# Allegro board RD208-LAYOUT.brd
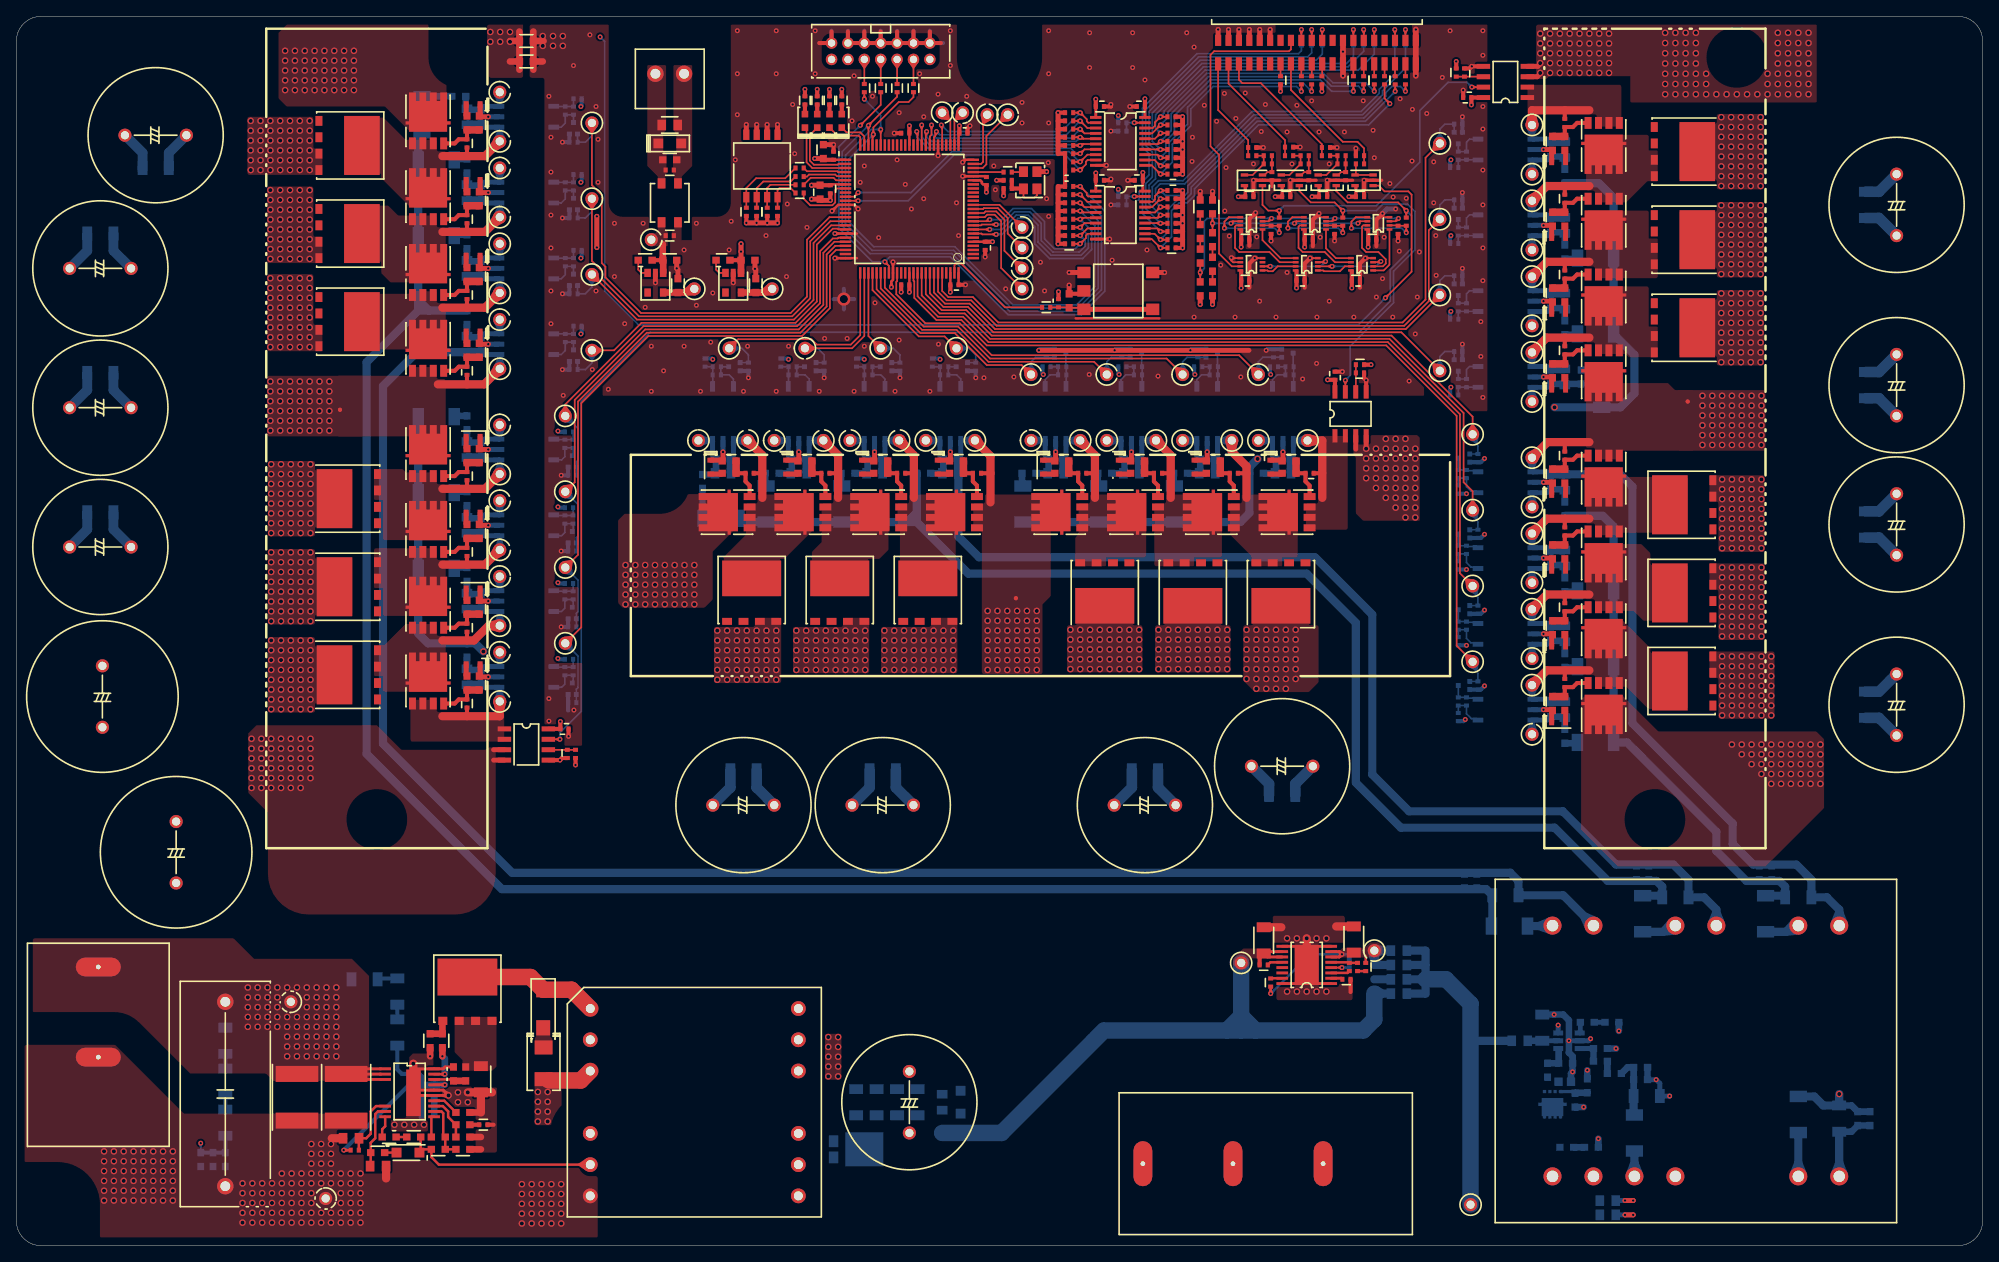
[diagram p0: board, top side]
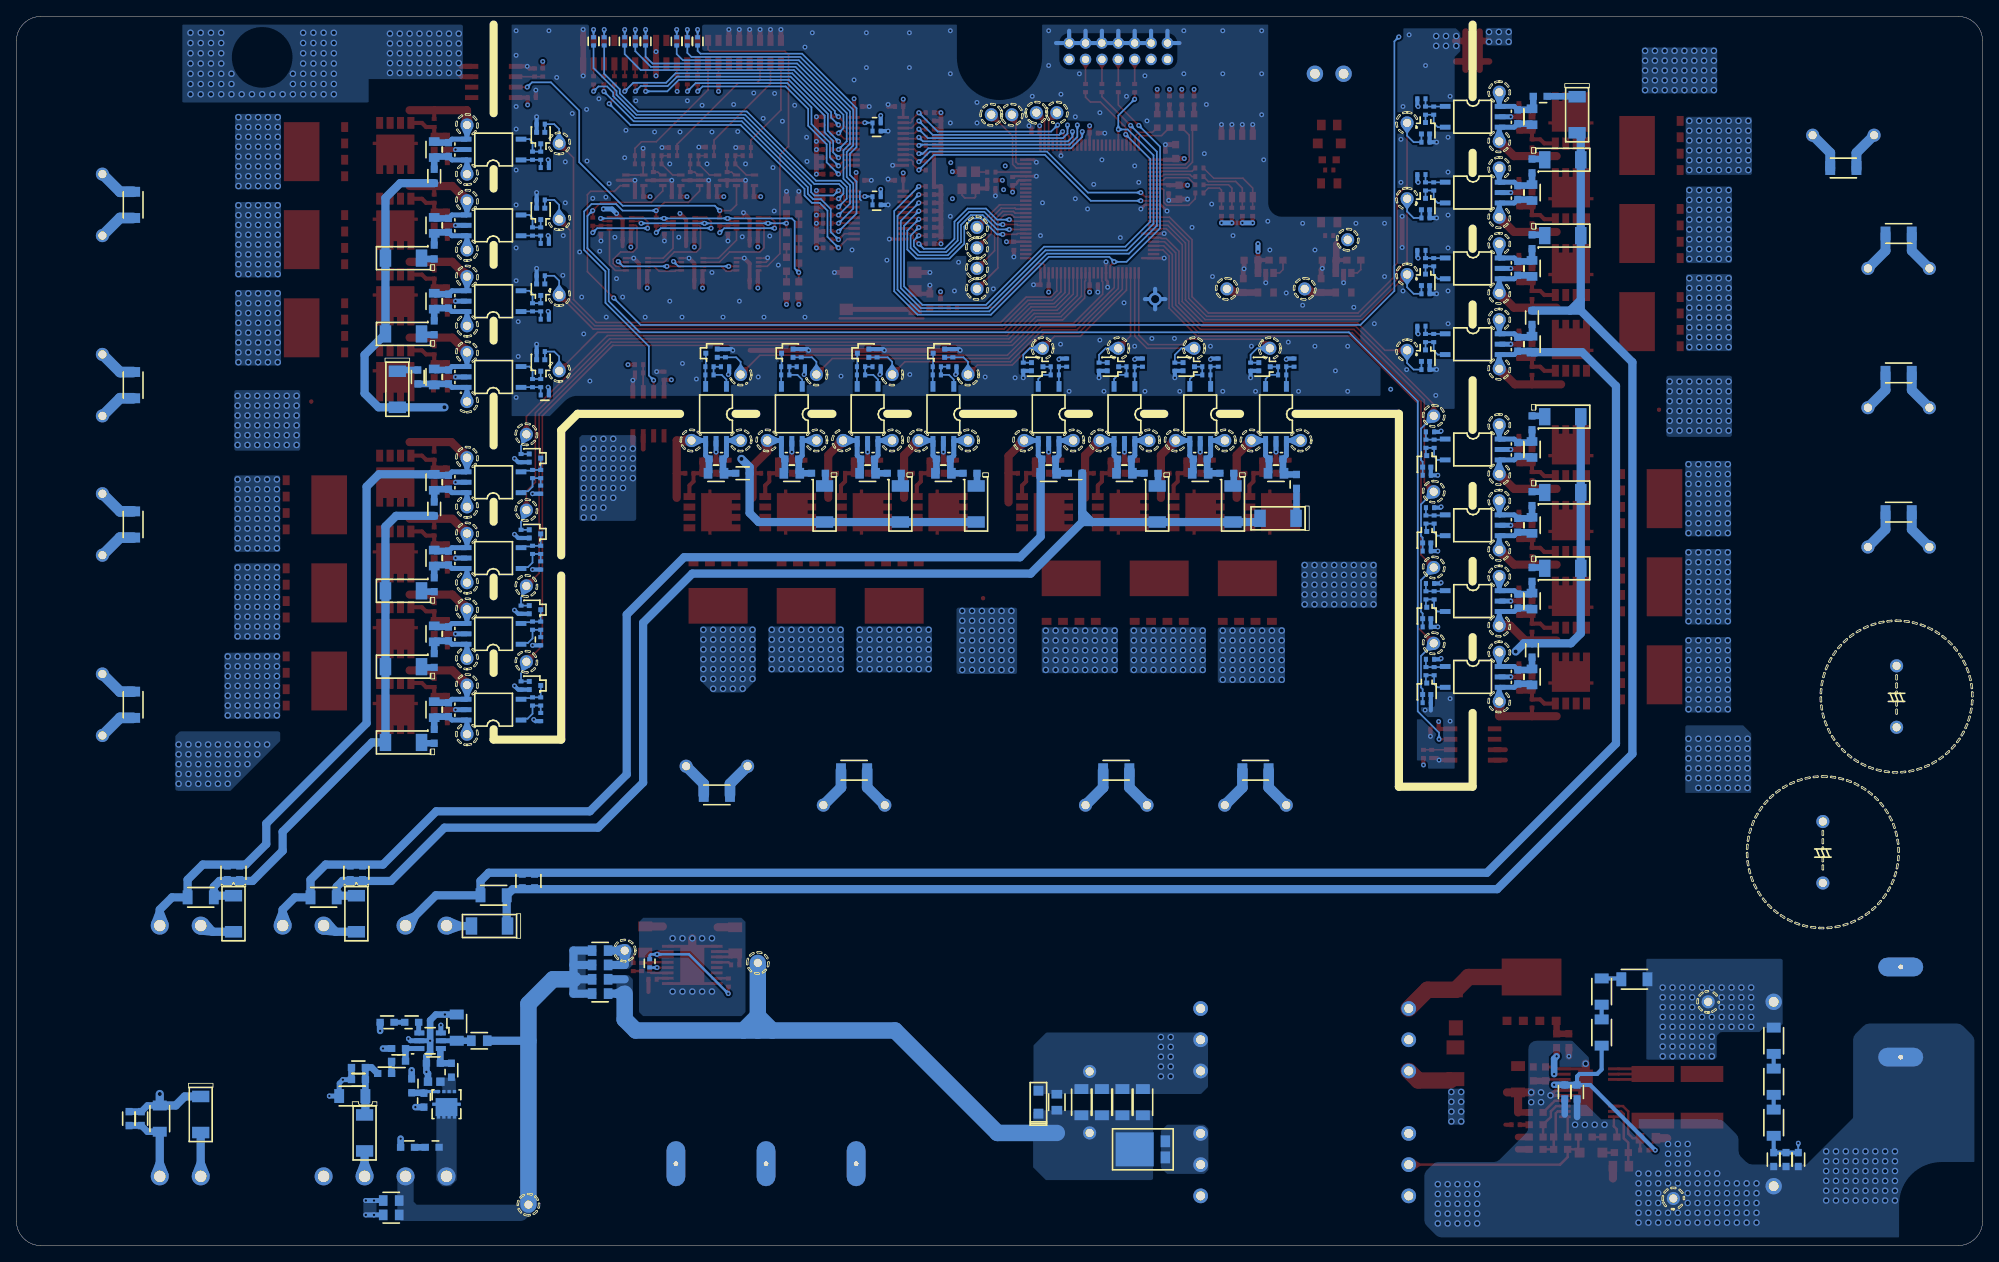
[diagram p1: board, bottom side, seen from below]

Outline 240 x 150 mm; copper layers: TOP, CONDUCTIVE2, CONDUCTIVE3, CONDUCTIVE4, CONDUCTIVE5, BOTTOM. Coordinates in mm from the lower left corner of the outline.
Outline path: 0,147 0.05,147.52 0.18,148.03 0.4,148.5 0.7,148.93 1.07,149.3 1.5,149.6 1.97,149.82 2.48,149.95 3,150 237,150 237.52,149.95 238.03,149.82 238.5,149.6 238.93,149.3 239.3,148.93 239.6,148.5 239.82,148.03 239.95,147.52 240,147 240,3 239.95,2.48 239.82,1.97 239.6,1.5 239.3,1.07 238.93,0.7 238.5,0.4 238.03,0.18 237.52,0.05 237,0 3,0 2.48,0.05 1.97,0.18 1.5,0.4 1.07,0.7 0.7,1.07 0.4,1.5 0.18,1.97 0.05,2.48 0,3 0,147

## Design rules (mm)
constraint set DEFAULT: 

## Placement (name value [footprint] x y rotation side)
C1  -  [C_27_0X10_5_P22_5_D__1]  25.5 18.5 270 top
C2  -  [C5750_R_SP]  34.25 18.1 270 top
C3  -  [C5750_R_SP]  40.25 18.1 270 top
C4  -  [C2125_R_SP]  44.15 9.7 0 top
C5  -  [C1608_R_SP]  48.5 13.25 180 top
C6  -  [C3216_R_SP]  102.5 17.5 90 bottom
C7  -  [CA_NICHEMI_D16_0_P7__1]  109 17.5 90 top
C8  -  [C1608_R_SP]  51 18.75 90 bottom
C9  -  [C3216_R_SP]  105 17.5 90 bottom
C10  -  [C1608_R_SP]  54.5 13.25 0 top
C11  -  [C1608_R_SP]  24 10.5 270 bottom
C12  -  [C1005_R_SP]  57 14.75 0 top
C13  -  [C1608_R_SP]  53.35 20.95 90 top
C14  -  [C2125_R_SP]  40.85 13.1 180 top
C15  -  [C3216_R_SP]  152.25 37.25 90 top
C16  -  [C3216_R_SP]  163.25 37.35 90 top
C17  -  [C3216_R_SP]  181.75 42.75 0 bottom
C18  -  [C3216_R_SP]  202.5 42.5 0 bottom
C19  -  [C3216_R_SP]  217.5 42.5 0 bottom
C20  -  [C3216_R_SP]  222.5 15.5 270 bottom
C21  -  [C3216_R_SP]  199 18.25 0 bottom
C22  -  [C1608_R_SP]  191.75 27.25 0 bottom
C23  -  [C1608_R_SP]  79.75 132.5 0 top
C24  -  [C1005_R_SP]  79.75 131.25 0 top
C25  -  [C1608_R_SP]  90.25 117.15 90 top
C27  -  [C1005_R_SP]  79.75 123.25 0 top
C28  -  [C1608_R_SP]  89.3 120.25 0 top
C29  -  [C1608_R_SP]  79.75 120.25 0 top
C30  -  [C1608_R_SP]  80.75 117.15 90 top
C31  -  [C1608_R_SP]  98.5 133.5 90 top
C32  -  [C1005_R_SP]  118.25 122 270 top
C33  -  [C1005_R_SP]  118.4 129.9 90 top
C34  -  [C1005_R_SP]  108.5 135.75 180 top
C35  -  [C1005_R_SP]  99.75 133 90 top
C36  -  [C1005_R_SP]  108.5 117.25 180 top
C37  -  [C1005_R_SP]  114.5 117.25 0 top
C38  -  [C1005_R_SP]  137 130 180 top
C39  -  [C1005_R_SP]  132.25 130 0 top
C40  -  [C1608_R_SP]  98.1 128.55 270 top
C41  -  [C1005_R_SP]  99.35 128.9 270 top
C42  -  [C1005_R_SP]  115.6 135.75 0 top
C43  -  [C1005_R_SP]  137.25 139 180 top
C44  -  [C1005_R_SP]  132.25 139 0 top
C45  -  [C1005_R_SP]  164 128 0 top
C46  -  [C1005_R_SP]  121 129 180 top
C47  -  [C2125_R_SP]  55 137.75 270 bottom
C48  -  [CA_NICHEMI_D16_0_P7__1]  17 135.5 0 top
C49  -  [CA_NICHEMI_D16_0_P7__1]  10.25 119.25 0 top
C50  -  [C2125_R_SP]  55 128.5 270 bottom
C53  -  [C2125_R_SP]  55 119.25 270 bottom
C54  -  [CA_NICHEMI_D16_0_P7__1]  10.25 102.25 0 top
C55  -  [C2125_R_SP]  55 110 270 bottom
C56  -  [CA_NICHEMI_D16_0_P7__1]  10.25 85.25 0 top
C57  -  [C2125_R_SP]  55 97.15 270 bottom
C58  -  [C2125_R_SP]  55 87.9 270 bottom
C59  -  [C2125_R_SP]  55 78.65 270 bottom
C60  -  [C2125_R_SP]  55 69.4 270 bottom
C61  -  [C1005_R_SP]  66.9 63.05 0 top
C62  -  [C2125_R_SP]  86.25 94.25 0 bottom
C63  -  [CA_NICHEMI_D16_0_P7__1]  88.75 53.75 0 top
C64  -  [C2125_R_SP]  95.5 94.25 0 bottom
C65  -  [CA_NICHEMI_D16_0_P7__1]  105.75 53.75 0 top
C66  -  [CA_D18_0_P7_5_D_SP]  19.5 48 90 top
C67  -  [CA_D18_0_P7_5_D_SP]  10.5 67 90 top
C68  -  [C2125_R_SP]  104.75 94.25 0 bottom
C69  -  [CA_NICHEMI_D16_0_P7__1]  137.75 53.75 0 top
C70  -  [C2125_R_SP]  114 94.25 0 bottom
C71  -  [CA_NICHEMI_D16_0_P7__1]  154.5 58.5 0 top
C72  -  [C2125_R_SP]  126.85 94.25 0 bottom
C73  -  [C2125_R_SP]  136.1 94.25 0 bottom
C74  -  [C2125_R_SP]  145.35 94.25 0 bottom
C75  -  [C1005_R_SP]  160.95 106.15 90 top
C76  -  [C2125_R_SP]  154.6 94.25 0 bottom
C77  -  [C2125_R_SP]  189 65.4 90 bottom
C78  -  [CA_NICHEMI_D16_0_P7__1]  229.5 66 90 top
C79  -  [C2125_R_SP]  189 74.65 90 bottom
C80  -  [CA_NICHEMI_D16_0_P7__1]  229.5 88 90 top
C81  -  [C2125_R_SP]  189 83.9 90 bottom
C82  -  [CA_NICHEMI_D16_0_P7__1]  229.5 105 90 top
C83  -  [C2125_R_SP]  189 93.15 90 bottom
C84  -  [CA_NICHEMI_D16_0_P7__1]  229.5 127 90 top
C85  -  [C2125_R_SP]  189 106 90 bottom
C86  -  [C2125_R_SP]  189 115.25 90 bottom
C87  -  [C2125_R_SP]  189 124.5 90 bottom
C88  -  [C2125_R_SP]  189 133.75 90 bottom
C89  -  [C1005_R_SP]  177.1 140.1 180 top
C90  -  [C1005_R_SP]  165.5 122.75 0 top
C91  -  [C1005_R_SP]  163.5 117.75 0 top
C92  -  [C1005_R_SP]  157.75 122.75 0 top
C93  -  [C1005_R_SP]  156.75 117.75 0 top
C94  -  [C1005_R_SP]  150 117.75 0 top
C95  -  [C1005_R_SP]  150 122.75 0 top
C96  -  [C1005_R_SP]  161.75 132 0 top
C97  -  [C1005_R_SP]  159.5 128 0 top
C98  -  [C1005_R_SP]  157.25 132 0 top
C99  -  [C1005_R_SP]  155 128 0 top
C100  -  [C1005_R_SP]  152.75 132 0 top
C101  -  [C1005_R_SP]  150.5 128 0 top
C102  -  [C1608_R_SP]  128.5 115.3 90 top
C103  -  [C1608_R_SP]  189.1 22.25 0 bottom
C104  -  [C1608_R_SP]  86.25 96 0 bottom
C105  -  [C1608_R_SP]  95.5 96 0 bottom
C106  -  [C1608_R_SP]  104.75 96 0 bottom
C107  -  [C1608_R_SP]  114 96 0 bottom
C108  -  [C1608_R_SP]  126.85 96 0 bottom
C109  -  [C1608_R_SP]  136.1 96 0 bottom
C110  -  [C1608_R_SP]  145.35 96 0 bottom
C111  -  [C1608_R_SP]  154.6 96 0 bottom
C112  -  [C1608_R_SP]  56.75 137.75 270 bottom
C113  -  [C1608_R_SP]  56.75 128.5 270 bottom
C114  -  [C1608_R_SP]  56.75 119.25 270 bottom
C115  -  [C1608_R_SP]  56.75 110 270 bottom
C116  -  [C1608_R_SP]  56.75 97.15 270 bottom
C117  -  [C1608_R_SP]  56.75 87.9 270 bottom
C118  -  [C1608_R_SP]  56.75 78.65 270 bottom
C119  -  [C1608_R_SP]  56.75 69.4 270 bottom
C120  -  [C1608_R_SP]  187.25 65.4 90 bottom
C121  -  [C1608_R_SP]  187.25 74.65 90 bottom
C122  -  [C1608_R_SP]  187.25 83.9 90 bottom
C123  -  [C1608_R_SP]  187.25 93.15 90 bottom
C124  -  [C1608_R_SP]  187.25 106 90 bottom
C125  -  [C1608_R_SP]  187.25 115.25 90 bottom
C126  -  [C1608_R_SP]  187.25 124.5 90 bottom
C127  -  [C1608_R_SP]  187.25 133.75 90 bottom
C128  -  [C1608_R_SP]  189.25 12 0 bottom
C129  -  [C3216_R_SP]  186.25 26.6 90 bottom
C130  -  [C1608_R_SP]  22.5 10.5 270 bottom
C131  -  [C3216_R_SP]  107.5 17.5 90 bottom
C132  -  [C3216_R_SP]  110 17.5 90 bottom
C133  -  [C1005_R_SP]  164 133 180 top
C134  -  [C1005_R_SP]  159.85 134 0 top
C135  -  [C1005_R_SP]  155.35 134.05 0 top
C136  -  [C1005_R_SP]  150.85 134 0 top
C137  -  [C2125_R_SP]  194.25 3.75 0 bottom
C138  -  [C2125_R_SP]  194.25 5.5 0 bottom
C139  -  [C1005_R_SP]  168.65 123.95 270 top
C140  -  [C1005_R_SP]  160.9 123.95 270 top
C141  -  [C1005_R_SP]  153.15 123.95 270 top
C142  -  [C1005_R_SP]  68 138.5 270 bottom
C143  -  [C1005_R_SP]  68 129.25 270 bottom
C144  -  [C1005_R_SP]  68 120 270 bottom
C145  -  [C1005_R_SP]  68 110.75 270 bottom
C146  -  [C1005_R_SP]  67.95 97.85 270 bottom
C147  -  [C1005_R_SP]  67.95 88.6 270 bottom
C148  -  [C1005_R_SP]  67.95 79.35 270 bottom
C149  -  [C1005_R_SP]  67.95 70.1 270 bottom
C150  -  [C1005_R_SP]  85.5 107.25 0 bottom
C151  -  [C1005_R_SP]  94.75 107.25 0 bottom
C152  -  [C1005_R_SP]  104 107.25 0 bottom
C153  -  [C1005_R_SP]  113.25 107.25 0 bottom
C154  -  [C1005_R_SP]  127.65 107.25 0 bottom
C155  -  [C1005_R_SP]  136.9 107.25 0 bottom
C156  -  [C1005_R_SP]  146.15 107.25 0 bottom
C157  -  [C1005_R_SP]  155.4 107.25 0 bottom
C158  -  [C1005_R_SP]  176 66.4 90 bottom
C159  -  [C1005_R_SP]  176 75.65 90 bottom
C160  -  [C1005_R_SP]  176 84.9 90 bottom
C161  -  [C1005_R_SP]  176 94.15 90 bottom
C162  -  [C1005_R_SP]  176 105.25 90 bottom
C163  -  [C1005_R_SP]  176 114.5 90 bottom
C164  -  [C1005_R_SP]  176 123.75 90 bottom
C165  -  [C1005_R_SP]  176 133 90 bottom
CN1  -  [OTB_640NS_B_2P_C_D_S_1]  10 34 270 top
CN2  -  [1843606_D_SP]  79.75 143 0 top
CN3  -  [FTSH_120_04_X_DH_A_A_1]  158.75 150.45 0 top
CN4  -  [878311420_D_SP]  105.5 145.75 180 top
CN5  -  [OTB_640NS_B_3P_C_D_S_1]  137.5 10 0 top
D1  -  [TO_3_2A1A_12_R_SP]  47.8 11.35 180 top
D2  -  [ON_TO_227_3LD_123_R__1]  102.5 11.75 180 bottom
D3  -  [TO_3_2A1S_R_SP]  115.25 17.5 270 bottom
D4  -  [VISHAY_DO_214AA_R_SP]  64.35 22.25 90 top
D6  -  [DIODES_D_FLAT_R_SP]  64.3 28.9 270 top
D7  -  [TO_3_4E1A_R_SP]  182.25 39 180 bottom
D8  -  [TO_3_4E1A_R_SP]  198.5 40.5 90 bottom
D9  -  [TO_3_4E1A_R_SP]  213.5 40.5 90 bottom
D10  -  [TO_3_4E1A_R_SP]  197.5 13.75 90 bottom
D11  -  [TO_3_4E1A_R_SP]  217.5 16 90 bottom
D13  -  [TO_3_2A1S_R_SP]  79.75 134.5 180 top
D14  -  [TO_3_4E1S_R_SP]  49.5 138 90 bottom
D15  -  [ON_PQFN4_8X8_2P_R_SP]  40.75 134.25 270 top
D16  -  [TO_3_4E1S_R_SP]  51.25 132.5 0 bottom
D17  -  [ON_PQFN4_8X8_2P_R_SP]  40.75 123.5 270 top
D18  -  [TO_3_4E1S_R_SP]  51.25 123.25 0 bottom
D19  -  [ON_PQFN4_8X8_2P_R_SP]  40.75 112.75 270 top
D20  -  [TO_3_4E1S_R_SP]  51.25 101.15 0 bottom
D21  -  [ON_PQFN4_8X8_2P_R_SP]  40.25 91.15 90 top
D22  -  [TO_3_4E1S_R_SP]  51.25 91.9 0 bottom
D23  -  [ON_PQFN4_8X8_2P_R_SP]  40.25 80.4 90 top
D24  -  [TO_3_4E1S_R_SP]  51.25 82.65 0 bottom
D25  -  [ON_PQFN4_8X8_2P_R_SP]  40.25 69.65 90 top
D26  -  [TO_3_4E1S_R_SP]  86 88.75 180 bottom
D27  -  [ON_PQFN4_8X8_2P_R_SP]  89.75 80 0 top
D28  -  [TO_3_4E1S_R_SP]  91.5 90.5 90 bottom
D29  -  [ON_PQFN4_8X8_2P_R_SP]  100.5 80 0 top
D30  -  [TO_3_4E1S_R_SP]  100.75 90.5 90 bottom
D31  -  [ON_PQFN4_8X8_2P_R_SP]  111.25 80 0 top
D32  -  [TO_3_4E1S_R_SP]  122.85 90.5 90 bottom
D33  -  [ON_PQFN4_8X8_2P_R_SP]  132.85 79.5 180 top
D34  -  [TO_3_4E1S_R_SP]  132.1 90.5 90 bottom
D35  -  [ON_PQFN4_8X8_2P_R_SP]  143.6 79.5 180 top
D36  -  [TO_3_4E1S_R_SP]  141.35 90.5 90 bottom
D37  -  [ON_PQFN4_8X8_2P_R_SP]  154.35 79.5 180 top
D38  -  [TO_3_4E1S_R_SP]  192.75 61.4 180 bottom
D39  -  [ON_PQFN4_8X8_2P_R_SP]  203.25 68.9 90 top
D40  -  [TO_3_4E1S_R_SP]  192.75 70.65 180 bottom
D41  -  [ON_PQFN4_8X8_2P_R_SP]  203.25 79.65 90 top
D42  -  [TO_3_4E1S_R_SP]  192.75 79.9 180 bottom
D43  -  [ON_PQFN4_8X8_2P_R_SP]  203.25 90.4 90 top
D44  -  [TO_3_4E1S_R_SP]  193.5 104.5 90 bottom
D45  -  [ON_PQFN4_8X8_2P_R_SP]  203.75 112 270 top
D46  -  [TO_3_4E1S_R_SP]  192.75 111.25 180 bottom
D47  -  [ON_PQFN4_8X8_2P_R_SP]  203.75 122.75 270 top
D48  -  [TO_3_4E1S_R_SP]  192.75 120.5 180 bottom
D49  -  [ON_PQFN4_8X8_2P_R_SP]  203.75 133.5 270 top
D50  -  [TO_ESC_R_SP]  55.75 139.25 0 top
D51  -  [TO_ESC_R_SP]  55.75 130 0 top
D52  -  [TO_ESC_R_SP]  55.75 120.75 0 top
D53  -  [TO_ESC_R_SP]  55.75 111.5 0 top
D54  -  [TO_ESC_R_SP]  55.75 98.65 0 top
D55  -  [TO_ESC_R_SP]  55.75 89.4 0 top
D56  -  [TO_ESC_R_SP]  55.75 80.15 0 top
D57  -  [TO_ESC_R_SP]  55.75 70.9 0 top
D58  -  [TO_ESC_R_SP]  84.75 95 90 top
D59  -  [TO_ESC_R_SP]  94 95 90 top
D60  -  [TO_ESC_R_SP]  103.25 95 90 top
D61  -  [TO_ESC_R_SP]  125.35 95 90 top
D62  -  [TO_ESC_R_SP]  112.5 95 90 top
D63  -  [TO_ESC_R_SP]  134.6 95 90 top
D64  -  [TO_ESC_R_SP]  143.85 95 90 top
D65  -  [TO_ESC_R_SP]  153.1 95 90 top
D66  -  [TO_ESC_R_SP]  188.25 63.9 180 top
D67  -  [TO_ESC_R_SP]  188.25 73.15 180 top
D68  -  [TO_ESC_R_SP]  188.25 82.4 180 top
D69  -  [TO_ESC_R_SP]  188.25 91.65 180 top
D70  -  [TO_ESC_R_SP]  188.25 104.5 180 top
D71  -  [TO_ESC_R_SP]  188.25 113.75 180 top
D72  -  [TO_ESC_R_SP]  188.25 123 180 top
D73  -  [TO_ESC_R_SP]  188.25 132.25 180 top
DR1  -  [ONEPOINT_R_SP]  39.5 102 270 top
DR2  -  [ONEPOINT_R_SP]  122 79 270 top
DR3  -  [ONEPOINT_R_SP]  204 103 0 top
DS1  -  [D_ROHM_1608_R_SP]  100.75 137.25 270 top
DS2  -  [D_ROHM_1608_R_SP]  99.25 137.25 270 top
DS3  -  [D_ROHM_1608_R_SP]  97.75 137.25 270 top
DS4  -  [D_ROHM_1608_R_SP]  96.25 137.25 270 top
FL1  -  [TDK_ACM4520_R_SP]  79.75 127.25 270 top
IC1  -  [LT_20_LEAD_PLASTIC_T_1]  48 18.65 270 top
IC2  -  [LT_TSSOP_16_FE_R_SP]  157.5 34.25 90 top
IC3  -  [LT_TSOT_23_6_R_SP]  189.5 25 270 bottom
IC4  -  [TO_SSOP5_P_0_95_R_SP]  87.5 117.5 180 top
IC5  -  [TO_SSOP5_P_0_95_R_SP]  78 117.5 180 top
IC6  -  [TO_TSSOP20B_R_SP]  134.75 125.75 270 top
IC7  -  [XI_VQFP100_R_SP]  109 126.5 90 top
IC8  -  [TO_TSSOP20B_R_SP]  134.75 134.75 270 top
IC9  -  [TI_DCK5_R_SP]  164.5 130 90 top
IC10  -  [TI_D8_R_SP]  62.25 61.15 270 top
IC11  -  [TI_D8_R_SP]  162.85 101.5 0 top
IC12  -  [TI_D8_R_SP]  181.75 142 90 top
IC13  -  [TO_SSOP8_P_0_50A_R_S_1]  166.25 124.75 90 top
IC14  -  [TO_SSOP8_P_0_50A_R_S_1]  164.25 119.75 90 top
IC15  -  [TO_SSOP8_P_0_50A_R_S_1]  158.5 124.75 90 top
IC16  -  [TO_SSOP8_P_0_50A_R_S_1]  150.75 119.75 90 top
IC17  -  [TO_SSOP8_P_0_50A_R_S_1]  157.5 119.75 90 top
IC18  -  [TO_SSOP8_P_0_50A_R_S_1]  150.75 124.75 90 top
IC19  -  [TI_DCK5_R_SP]  160 130 90 top
IC20  -  [TI_DCK5_R_SP]  155.5 130 90 top
IC21  -  [TI_DCK5_R_SP]  151 130 90 top
IC22  -  [ABRACON_ASE_3_2X2_5__1]  123.75 130 90 top
NOREF  -  []  156 10.38 90 top
NOREF#2  -  []  141 10.38 90 top
NOREF#3  -  []  111 36 0 top
PC1  -  [TO_11_4L1S_R_SP]  62.25 137.75 270 bottom
PC2  -  [TO_11_4L1S_R_SP]  62.25 128.5 270 bottom
PC3  -  [TO_11_4L1S_R_SP]  62.25 119.25 270 bottom
PC4  -  [TO_11_4L1S_R_SP]  62.25 110 270 bottom
PC5  -  [TO_11_4L1S_R_SP]  62.25 97.15 270 bottom
PC6  -  [TO_11_4L1S_R_SP]  62.25 87.9 270 bottom
PC7  -  [TO_11_4L1S_R_SP]  62.25 78.65 270 bottom
PC8  -  [TO_11_4L1S_R_SP]  62.25 69.4 270 bottom
PC9  -  [TO_11_4L1S_R_SP]  86.25 101.5 0 bottom
PC10  -  [TO_11_4L1S_R_SP]  95.5 101.5 0 bottom
PC11  -  [TO_11_4L1S_R_SP]  104.75 101.5 0 bottom
PC12  -  [TO_11_4L1S_R_SP]  114 101.5 0 bottom
PC13  -  [TO_11_4L1S_R_SP]  126.85 101.5 0 bottom
PC14  -  [TO_11_4L1S_R_SP]  136.1 101.5 0 bottom
PC15  -  [TO_11_4L1S_R_SP]  145.35 101.5 0 bottom
PC16  -  [TO_11_4L1S_R_SP]  154.6 101.5 0 bottom
PC17  -  [TO_11_4L1S_R_SP]  181.75 65.4 90 bottom
PC18  -  [TO_11_4L1S_R_SP]  181.75 74.65 90 bottom
PC19  -  [TO_11_4L1S_R_SP]  181.75 83.9 90 bottom
PC20  -  [TO_11_4L1S_R_SP]  181.75 93.15 90 bottom
PC21  -  [TO_11_4L1S_R_SP]  181.75 106 90 bottom
PC22  -  [TO_11_4L1S_R_SP]  181.75 115.25 90 bottom
PC23  -  [TO_11_4L1S_R_SP]  181.75 124.5 90 bottom
PC24  -  [TO_11_4L1S_R_SP]  181.75 133.75 90 bottom
Q1  -  [TO_2_8T1A_R_SP]  55.05 31.35 0 top
Q2  -  [TO_2_3X1S_R_SP]  187.5 17.25 0 bottom
Q3  -  [TO_2_5W1A_R_SP]  50.25 137.25 0 top
Q4  -  [TO_2_2H1B_GSD_123_R__1]  68 136.35 180 bottom
Q5  -  [TO_2_5W1A_R_SP]  50.25 128 0 top
Q6  -  [TO_2_2H1B_GSD_123_R__1]  68 127.1 180 bottom
Q7  -  [TO_2_5W1A_R_SP]  50.25 118.75 0 top
Q8  -  [TO_2_2H1B_GSD_123_R__1]  68 117.85 180 bottom
Q9  -  [TO_2_5W1A_R_SP]  50.25 109.5 0 top
Q10  -  [TO_2_2H1B_GSD_123_R__1]  68 108.6 180 bottom
Q11  -  [TO_2_5W1A_R_SP]  50.25 96.65 0 top
Q12  -  [TO_2_2H1B_GSD_123_R__1]  67.85 95.7 180 bottom
Q13  -  [TO_2_5W1A_R_SP]  50.25 87.4 0 top
Q14  -  [TO_2_2H1B_GSD_123_R__1]  67.85 86.45 180 bottom
Q15  -  [TO_2_5W1A_R_SP]  50.25 78.15 0 top
Q16  -  [TO_2_2H1B_GSD_123_R__1]  67.85 77.2 180 bottom
Q17  -  [TO_2_5W1A_R_SP]  50.25 68.9 0 top
Q18  -  [TO_2_2H1B_GSD_123_R__1]  67.85 67.95 180 bottom
Q19  -  [TO_2_5W1A_R_SP]  86.75 89.5 90 top
Q20  -  [TO_2_2H1B_GSD_123_R__1]  87.65 107.25 270 bottom
Q21  -  [TO_2_5W1A_R_SP]  96 89.5 90 top
Q22  -  [TO_2_2H1B_GSD_123_R__1]  96.9 107.25 270 bottom
Q23  -  [TO_2_5W1A_R_SP]  105.25 89.5 90 top
Q24  -  [TO_2_2H1B_GSD_123_R__1]  106.15 107.25 270 bottom
Q25  -  [TO_2_5W1A_R_SP]  114.5 89.5 90 top
Q26  -  [TO_2_2H1B_GSD_123_R__1]  115.4 107.25 270 bottom
Q27  -  [TO_2_5W1A_R_SP]  127.35 89.5 90 top
Q28  -  [TO_2_2H1B_GSD_123_R__1]  127.4 108.9 90 bottom
Q29  -  [TO_2_5W1A_R_SP]  136.6 89.5 90 top
Q30  -  [TO_2_2H1B_GSD_123_R__1]  136.65 108.9 90 bottom
Q31  -  [TO_2_5W1A_R_SP]  145.85 89.5 90 top
Q32  -  [TO_2_2H1B_GSD_123_R__1]  145.9 108.9 90 bottom
Q33  -  [TO_2_5W1A_R_SP]  155.1 89.5 90 top
Q34  -  [TO_2_2H1B_GSD_123_R__1]  155.15 108.9 90 bottom
Q35  -  [TO_2_5W1A_R_SP]  193.75 65.9 180 top
Q36  -  [TO_2_2H1B_GSD_123_R__1]  176.7 68.35 270 bottom
Q37  -  [TO_2_5W1A_R_SP]  193.75 75.15 180 top
Q38  -  [TO_2_2H1B_GSD_123_R__1]  176.7 77.6 270 bottom
Q39  -  [TO_2_5W1A_R_SP]  193.75 84.4 180 top
Q40  -  [TO_2_2H1B_GSD_123_R__1]  176.7 86.85 270 bottom
Q41  -  [TO_2_5W1A_R_SP]  193.75 93.65 180 top
Q42  -  [TO_2_2H1B_GSD_123_R__1]  176.7 96.1 270 bottom
Q43  -  [TO_2_5W1A_R_SP]  193.75 106.5 180 top
Q44  -  [TO_2_2H1B_GSD_123_R__1]  176 107.4 0 bottom
Q45  -  [TO_2_5W1A_R_SP]  193.75 115.75 180 top
Q46  -  [TO_2_2H1B_GSD_123_R__1]  176 116.65 0 bottom
Q47  -  [TO_2_5W1A_R_SP]  193.75 125 180 top
Q48  -  [TO_2_2H1B_GSD_123_R__1]  176 125.9 0 bottom
Q49  -  [TO_2_5W1A_R_SP]  193.75 134.25 180 top
Q50  -  [TO_2_2H1B_GSD_123_R__1]  176 135.15 0 bottom
R1  -  [R3216_R_SP]  42.5 32.5 0 bottom
R2  -  [R1608_R_SP]  44.1 11.35 0 top
R3  -  [R3216_R_SP]  46.5 31 270 bottom
R4  -  [R1608_R_SP]  45.5 13.25 180 top
R5  -  [R3216_R_SP]  25.5 25 270 bottom
R6  -  [R1608_R_SP]  51.5 11.75 0 top
R7  -  [R3216_R_SP]  46.5 26 270 bottom
R8  -  [R2125_R_SP]  113 17.5 270 bottom
R9  -  [R3216_R_SP]  25.5 20 270 bottom
R10  -  [R3216_R_SP]  25.5 15 270 bottom
R11  -  [R1608_R_SP]  49.5 18.75 90 bottom
R12  -  [R1608_R_SP]  51.5 13.25 180 top
R13  -  [R1608_R_SP]  54.5 11.75 0 top
R14  -  [R1608_R_SP]  54.5 14.75 0 top
R15  -  [R1608_R_SP]  25.5 10.5 270 bottom
R16  -  [R1608_R_SP]  54.5 16.25 180 top
R17  -  [R1608_R_SP]  52 25 90 top
R18  -  [R1608_R_SP]  54.85 20.95 90 top
R19  -  [R3216_R_SP]  56.7 20.3 270 top
R20  -  [R2125_R_SP]  168.75 30.75 0 bottom
R21  -  [R2125_R_SP]  168.75 36 0 bottom
R22  -  [R1005_R_SP]  152.25 34.25 0 top
R23  -  [R2125_R_SP]  168.75 32.5 0 bottom
R24  -  [R1005_R_SP]  164.7 34 90 top
R25  -  [R2125_R_SP]  168.75 34.25 0 bottom
R26  -  [R1005_R_SP]  162.35 32.5 0 top
R27  -  [R1005_R_SP]  163.7 34 90 top
R28  -  [R1608_R_SP]  195.05 21 180 bottom
R29  -  [R1608_R_SP]  193.35 22.5 180 bottom
R30  -  [R1608_R_SP]  186.9 21.4 270 bottom
R31  -  [R1608_R_SP]  198.25 20.25 0 bottom
R32  -  [R1608_R_SP]  194.75 27.25 0 bottom
R33  -  [R_WSL0603_R_SP]  189 20 0 bottom
R34  -  [R1608_R_SP]  193.35 24.05 0 bottom
R36  -  [R1608_R_SP]  86.25 120.25 180 top
R39  -  [R1608_R_SP]  76.75 120.25 180 top
R40  -  [R1005_R_SP]  141 128.75 180 top
R41  -  [R1005_R_SP]  141 127.75 180 top
R42  -  [R1005_R_SP]  141 126.75 180 top
R43  -  [R1005_R_SP]  141 125.75 180 top
R44  -  [R1005_R_SP]  141 124.75 180 top
R45  -  [R1005_R_SP]  141 123.75 180 top
R46  -  [R1005_R_SP]  141 122.75 180 top
R47  -  [R1005_R_SP]  141 121.75 180 top
R48  -  [R1005_R_SP]  128.5 129.25 0 top
R49  -  [R1005_R_SP]  128.5 128.25 0 top
R50  -  [R1005_R_SP]  128.5 127.25 0 top
R51  -  [R1005_R_SP]  128.5 126.25 0 top
R52  -  [R1005_R_SP]  128.5 125.25 0 top
R53  -  [R1005_R_SP]  128.5 124.25 0 top
R54  -  [R1005_R_SP]  128.5 123.25 0 top
R55  -  [R1005_R_SP]  128.5 122.25 0 top
R56  -  [R1005_R_SP]  159.35 142.2 270 top
R57  -  [R1005_R_SP]  154.3 142.2 270 top
R58  -  [R1005_R_SP]  141 137.75 180 top
R59  -  [R1005_R_SP]  141 136.75 180 top
R60  -  [R1005_R_SP]  141 135.75 180 top
R61  -  [R1005_R_SP]  141 134.75 180 top
R62  -  [R1005_R_SP]  141 133.75 180 top
R63  -  [R1005_R_SP]  141 132.75 180 top
R64  -  [R1005_R_SP]  141 131.75 180 top
R65  -  [R1005_R_SP]  141 130.75 180 top
R66  -  [R1005_R_SP]  128.5 138.25 0 top
R67  -  [R1005_R_SP]  128.5 137.25 0 top
R68  -  [R1005_R_SP]  128.5 136.25 0 top
R69  -  [R1005_R_SP]  128.5 135.25 0 top
R70  -  [R1005_R_SP]  128.5 134.25 0 top
R71  -  [R1005_R_SP]  128.5 133.25 0 top
R72  -  [R1005_R_SP]  128.5 132.25 0 top
R73  -  [R1005_R_SP]  128.5 131.25 0 top
R74  -  [R1005_R_SP]  121 130 0 top
R75  -  [R1005_R_SP]  107.5 141.25 270 top
R76  -  [R1005_R_SP]  109.5 141.25 270 top
R77  -  [R1005_R_SP]  105.5 141.25 270 top
R78  -  [R1005_R_SP]  103.5 141.25 270 top
R79  -  [R1005_R_SP]  121 131 180 top
R80  -  [R1608_R_SP]  54 140.25 180 bottom
R81  -  [R1005_R_SP]  68.5 139.95 180 bottom
R82  -  [R1608_R_SP]  55 131.75 90 bottom
R83  -  [R1005_R_SP]  68.5 130.7 180 bottom
R84  -  [R1608_R_SP]  55 122.5 90 bottom
R85  -  [R1005_R_SP]  68.5 121.45 180 bottom
R86  -  [R1608_R_SP]  55 113.25 90 bottom
R87  -  [R1005_R_SP]  68.5 112.2 180 bottom
R88  -  [R1608_R_SP]  55 100.4 90 bottom
R89  -  [R1005_R_SP]  67.45 99.3 0 bottom
R90  -  [R1608_R_SP]  55 91.15 90 bottom
R91  -  [R1005_R_SP]  67.45 90.05 0 bottom
R92  -  [R1608_R_SP]  55 81.9 90 bottom
R93  -  [R1005_R_SP]  67.45 80.8 0 bottom
R94  -  [R1608_R_SP]  55 72.65 90 bottom
R95  -  [R1005_R_SP]  67.45 71.55 0 bottom
R96  -  [R1608_R_SP]  83.75 93.25 270 bottom
R97  -  [R1005_R_SP]  84.05 107.75 270 bottom
R98  -  [R1608_R_SP]  92.25 94.25 180 bottom
R99  -  [R1005_R_SP]  93.3 107.75 270 bottom
R100  -  [R1005_R_SP]  102.55 107.75 270 bottom
R101  -  [R1608_R_SP]  101.5 94.25 180 bottom
R102  -  [R1005_R_SP]  111.8 107.75 270 bottom
R103  -  [R1608_R_SP]  110.75 94.25 180 bottom
R104  -  [R1608_R_SP]  123.6 94.25 180 bottom
R105  -  [R1005_R_SP]  125.75 107.25 0 bottom
R106  -  [R1608_R_SP]  132.85 94.25 180 bottom
R107  -  [R1005_R_SP]  135 107.25 0 bottom
R108  -  [R1608_R_SP]  142.1 94.25 180 bottom
R109  -  [R1005_R_SP]  144.25 107.25 0 bottom
R110  -  [R1608_R_SP]  151.35 94.25 180 bottom
R111  -  [R1005_R_SP]  153.5 107.25 0 bottom
R112  -  [R1608_R_SP]  189 62.15 270 bottom
R113  -  [R1005_R_SP]  176 64.5 90 bottom
R114  -  [R1608_R_SP]  189 71.4 270 bottom
R115  -  [R1005_R_SP]  176 73.75 90 bottom
R116  -  [R1608_R_SP]  189 80.65 270 bottom
R117  -  [R1005_R_SP]  176 83 90 bottom
R118  -  [R1608_R_SP]  189 89.9 270 bottom
R119  -  [R1005_R_SP]  176 92.25 90 bottom
R120  -  [R1608_R_SP]  191 106 90 bottom
R121  -  [R1005_R_SP]  175.5 103.8 0 bottom
R122  -  [R1608_R_SP]  189 112 270 bottom
R123  -  [R1005_R_SP]  175.5 113.05 0 bottom
R124  -  [R1608_R_SP]  189 121.25 270 bottom
R125  -  [R1005_R_SP]  175.5 122.3 0 bottom
R126  -  [R1608_R_SP]  189 130.5 270 bottom
R127  -  [R1005_R_SP]  175.5 131.55 0 bottom
R128  -  [R1608_R_SP]  146 116.75 90 top
R129  -  [R1608_R_SP]  144.5 116.75 90 top
R130  -  [R1608_R_SP]  146 119.75 90 top
R131  -  [R1608_R_SP]  144.5 120.75 90 top
R132  -  [R1608_R_SP]  146 122.75 90 top
R133  -  [R1608_R_SP]  144.5 123.75 90 top
R134  -  [R1608_R_SP]  146 126.75 90 top
R135  -  [R1608_R_SP]  144.5 126.75 90 top
R136  -  [R1005_R_SP]  161.75 133 0 top
R137  -  [R1005_R_SP]  159.85 133 0 top
R138  -  [R1005_R_SP]  162.25 130.5 90 top
R139  -  [R1005_R_SP]  157.25 133 0 top
R140  -  [R1005_R_SP]  155.35 133 0 top
R141  -  [R1005_R_SP]  157.75 130.5 90 top
R142  -  [R1005_R_SP]  152.75 133 0 top
R143  -  [R1005_R_SP]  150.85 133 0 top
R144  -  [R1005_R_SP]  153.25 130.5 90 top
R145  -  [R1005_R_SP]  100.75 139.75 270 top
R146  -  [R1005_R_SP]  99.25 139.75 270 top
R147  -  [R1005_R_SP]  97.75 139.75 270 top
R148  -  [R1005_R_SP]  96.25 139.75 270 top
R149  -  [R1005_R_SP]  89.1 126.15 90 top
R150  -  [R1005_R_SP]  90.35 126.15 90 top
R151  -  [R1005_R_SP]  91.65 126.15 90 top
R152  -  [R1005_R_SP]  92.9 126.15 90 top
R153  -  [R1005_R_SP]  127.2 115 270 top
R154  -  [R1608_R_SP]  191.75 19.5 270 bottom
R155  -  [R2125_R_SP]  183.5 25 0 bottom
R156  -  [R1005_R_SP]  169.55 142.2 270 top
R157  -  [R1005_R_SP]  165.75 142.2 270 top
R158  -  [R1005_R_SP]  164.45 142.2 270 top
R159  -  [R1005_R_SP]  163.2 142.2 270 top
R160  -  [R1005_R_SP]  169.55 146.95 90 bottom
R161  -  [R1005_R_SP]  168.25 146.95 90 bottom
R162  -  [R1005_R_SP]  165.75 146.95 90 bottom
R163  -  [R1005_R_SP]  164.45 146.95 90 bottom
R164  -  [R1005_R_SP]  163.2 146.95 90 bottom
R165  -  [R1005_R_SP]  159.4 146.95 90 bottom
R166  -  [R1005_R_SP]  158.1 146.95 90 bottom
R167  -  [R1005_R_SP]  156.85 146.95 90 bottom
R168  -  [R1608_R_SP]  87 95.75 0 top
R169  -  [R1608_R_SP]  96.25 95.75 0 top
R170  -  [R1608_R_SP]  105.5 95.75 0 top
R171  -  [R1608_R_SP]  114.75 95.75 0 top
R172  -  [R1608_R_SP]  127.6 95.75 0 top
R173  -  [R1608_R_SP]  136.85 95.75 0 top
R174  -  [R1608_R_SP]  146.1 95.75 0 top
R175  -  [R1608_R_SP]  155.35 95.75 0 top
R176  -  [R1608_R_SP]  56.5 137 270 top
R177  -  [R1608_R_SP]  56.5 127.75 270 top
R178  -  [R1608_R_SP]  56.5 118.5 270 top
R179  -  [R1608_R_SP]  56.5 109.25 270 top
R180  -  [R1608_R_SP]  56.5 96.4 270 top
R181  -  [R1608_R_SP]  56.5 87.15 270 top
R182  -  [R1608_R_SP]  56.5 77.9 270 top
R183  -  [R1608_R_SP]  56.5 68.65 270 top
R184  -  [R1608_R_SP]  187.5 66.15 90 top
R185  -  [R1608_R_SP]  187.5 75.4 90 top
R186  -  [R1608_R_SP]  187.5 84.65 90 top
R187  -  [R1608_R_SP]  187.5 93.9 90 top
R188  -  [R1608_R_SP]  187.5 106.75 90 top
R189  -  [R1608_R_SP]  187.5 116 90 top
R190  -  [R1608_R_SP]  187.5 125.25 90 top
R191  -  [R1608_R_SP]  187.5 134.5 90 top
R192  -  [R1005_R_SP]  164 132 0 top
R193  -  [R3216_R_SP]  17 131.5 0 bottom
R194  -  [R3216_R_SP]  10.25 123.5 0 bottom
R195  -  [R3216_R_SP]  10.25 106.5 0 bottom
R196  -  [R3216_R_SP]  10.25 89.5 0 bottom
R197  -  [R1608_R_SP]  192.25 12 0 bottom
R198  -  [R1005_R_SP]  168.3 142.2 270 top
R199  -  [R3216_R_SP]  88.75 58 0 bottom
R200  -  [R3216_R_SP]  105.75 58 0 bottom
R201  -  [R3216_R_SP]  137.75 58 0 bottom
R202  -  [R3216_R_SP]  154.5 55 0 bottom
R203  -  [R3216_R_SP]  225.75 66 90 bottom
R204  -  [R3216_R_SP]  225.75 88 90 bottom
R205  -  [R3216_R_SP]  225.75 105 90 bottom
R206  -  [R3216_R_SP]  225.75 127 90 bottom
R207  -  [R1608_R_SP]  50.5 25 270 top
R208  -  [R1608_R_SP]  190.25 17.75 270 bottom
R209  -  [R1005_R_SP]  125.7 114.5 180 top
R210  -  [R1005_R_SP]  95.6 131.5 0 top
R211  -  [R1005_R_SP]  95.6 130.45 0 top
R212  -  [R1005_R_SP]  95.6 129.45 0 top
R213  -  [R1005_R_SP]  95.6 128.45 0 top
R214  -  [R1005_R_SP]  55 134.5 270 top
R215  -  [R1005_R_SP]  55 125.25 270 top
R216  -  [R1005_R_SP]  55 116 270 top
R217  -  [R1005_R_SP]  55 106.75 270 top
R218  -  [R1005_R_SP]  55 93.9 270 top
R219  -  [R1005_R_SP]  55 84.65 270 top
R220  -  [R1005_R_SP]  55 75.4 270 top
R221  -  [R1005_R_SP]  55 66.15 270 top
R222  -  [R1005_R_SP]  89.5 94.25 0 top
R223  -  [R1005_R_SP]  98.75 94.25 0 top
R224  -  [R1005_R_SP]  108 94.25 0 top
R225  -  [R1005_R_SP]  117.25 94.25 0 top
R226  -  [R1005_R_SP]  130.1 94.25 0 top
R227  -  [R1005_R_SP]  139.35 94.25 0 top
R228  -  [R1005_R_SP]  148.6 94.25 0 top
R229  -  [R1005_R_SP]  157.85 94.25 0 top
R230  -  [R1005_R_SP]  189 68.65 90 top
R231  -  [R1005_R_SP]  189 77.9 90 top
R232  -  [R1005_R_SP]  189 87.15 90 top
R233  -  [R1005_R_SP]  189 96.4 90 top
R234  -  [R1005_R_SP]  189 109.25 90 top
R235  -  [R1005_R_SP]  189 118.5 90 top
R236  -  [R1005_R_SP]  189 127.75 90 top
R237  -  [R1005_R_SP]  189 137 90 top
R238  -  [R1005_R_SP]  167 142.2 270 top
R239  -  [R1005_R_SP]  158.1 142.2 270 top
R240  -  [R1005_R_SP]  156.85 142.2 270 top
R241  -  [R1005_R_SP]  135 128 0 bottom
R242  -  [R1005_R_SP]  135 127 0 bottom
R243  -  [R1005_R_SP]  135 137 0 bottom
R244  -  [R1005_R_SP]  135 136 0 bottom
R245  -  [R1608_R_SP]  55 137 270 top
R246  -  [R1608_R_SP]  55 127.75 270 top
R247  -  [R1608_R_SP]  55 118.5 270 top
R249  -  [R1608_R_SP]  55 109.25 270 top
R251  -  [R1608_R_SP]  55 96.4 270 top
R253  -  [R1608_R_SP]  55 87.15 270 top
R255  -  [R1608_R_SP]  55 77.9 270 top
R257  -  [R1608_R_SP]  55 68.65 270 top
R258  -  [R1608_R_SP]  87 94.25 0 top
R260  -  [R1608_R_SP]  96.25 94.25 0 top
R262  -  [R1608_R_SP]  105.5 94.25 0 top
R264  -  [R1608_R_SP]  127.6 94.25 0 top
R266  -  [R1608_R_SP]  114.75 94.25 0 top
R268  -  [R1608_R_SP]  136.85 94.25 0 top
R270  -  [R1608_R_SP]  146.1 94.25 0 top
R272  -  [R1608_R_SP]  155.35 94.25 0 top
R274  -  [R1608_R_SP]  189 66.15 90 top
R276  -  [R1608_R_SP]  189 75.4 90 top
R278  -  [R1608_R_SP]  189 84.65 90 top
R280  -  [R1608_R_SP]  189 93.9 90 top
R282  -  [R1608_R_SP]  189 106.75 90 top
R284  -  [R1608_R_SP]  189 116 90 top
R286  -  [R1608_R_SP]  189 125.25 90 top
R288  -  [R1608_R_SP]  189 134.5 90 top
R289  -  [R1005_R_SP]  68.25 60 270 top
R290  -  [R1005_R_SP]  67.25 60 270 top
R291  -  [R1005_R_SP]  164 107.5 0 top
R292  -  [R1005_R_SP]  164 106.5 180 top
R293  -  [R1005_R_SP]  175.75 143.15 90 top
R294  -  [R1005_R_SP]  176.75 143.15 270 top
R295  -  [R1005_R_SP]  153.1 32.1 90 top
R296  -  [R1005_R_SP]  162.7 34 90 top
R297  -  [R1005_R_SP]  162.7 34.45 90 bottom
R298  -  [R1608_R_SP]  62.25 147 180 top
R299  -  [R1608_R_SP]  62.25 144.5 180 top
R300  -  [R1608_R_SP]  198.25 21.75 0 bottom
R301  -  [R1608_R_SP]  178.25 44.5 90 bottom
R302  -  [R1608_R_SP]  176.75 44.5 90 bottom
R303  -  [R1608_R_SP]  199.25 45.5 90 bottom
R304  -  [R1608_R_SP]  197.75 45.5 90 bottom
R305  -  [R1608_R_SP]  214.25 45.5 90 bottom
R306  -  [R1608_R_SP]  212.75 45.5 90 bottom
R307  -  [R1608_R_SP]  224.75 15.5 270 bottom
R308  -  [R1608_R_SP]  226.25 15.5 270 bottom
R309  -  [R1005_R_SP]  169.65 124.95 90 top
R310  -  [R1005_R_SP]  161.9 124.95 90 top
R311  -  [R1005_R_SP]  154.15 124.95 90 top
R312  -  [R1005_R_SP]  41.3 11.65 180 top
R313  -  [R1005_R_SP]  68 134.65 180 bottom
R314  -  [R1005_R_SP]  68 125.4 180 bottom
R315  -  [R1005_R_SP]  68 116.15 180 bottom
R316  -  [R1005_R_SP]  68 106.9 180 bottom
R317  -  [R1005_R_SP]  67.85 94 180 bottom
R318  -  [R1005_R_SP]  67.85 84.75 180 bottom
R319  -  [R1005_R_SP]  67.85 75.5 180 bottom
R320  -  [R1005_R_SP]  67.85 66.25 180 bottom
R321  -  [R1005_R_SP]  89.35 107.25 270 bottom
R322  -  [R1005_R_SP]  98.6 107.25 270 bottom
R323  -  [R1005_R_SP]  107.85 107.25 270 bottom
R324  -  [R1005_R_SP]  117.1 107.25 270 bottom
R325  -  [R1005_R_SP]  125.7 108.9 90 bottom
R326  -  [R1005_R_SP]  134.95 108.9 90 bottom
R327  -  [R1005_R_SP]  144.2 108.9 90 bottom
R328  -  [R1005_R_SP]  153.45 108.9 90 bottom
R329  -  [R1005_R_SP]  178.4 68.35 270 bottom
R330  -  [R1005_R_SP]  178.4 77.6 270 bottom
R331  -  [R1005_R_SP]  178.4 86.85 270 bottom
R332  -  [R1005_R_SP]  178.4 96.1 270 bottom
R333  -  [R1005_R_SP]  176 109.1 0 bottom
R334  -  [R1005_R_SP]  176 118.35 0 bottom
R335  -  [R1005_R_SP]  176 127.6 0 bottom
R336  -  [R1005_R_SP]  176 136.85 0 bottom
R337  -  [R1005_R_SP]  67 138.5 270 bottom
R338  -  [R1005_R_SP]  67 129.25 270 bottom
R339  -  [R1005_R_SP]  67 120 270 bottom
R340  -  [R1005_R_SP]  67 110.75 270 bottom
R341  -  [R1005_R_SP]  66.95 97.85 270 bottom
R342  -  [R1005_R_SP]  66.95 88.6 270 bottom
R343  -  [R1005_R_SP]  66.95 79.35 270 bottom
R344  -  [R1005_R_SP]  66.95 70.1 270 bottom
R345  -  [R1005_R_SP]  85.5 106.25 0 bottom
R346  -  [R1005_R_SP]  94.75 106.25 0 bottom
R347  -  [R1005_R_SP]  104 106.25 0 bottom
R348  -  [R1005_R_SP]  113.25 106.25 0 bottom
R349  -  [R1005_R_SP]  127.65 106.25 0 bottom
R350  -  [R1005_R_SP]  136.9 106.25 0 bottom
R351  -  [R1005_R_SP]  146.15 106.25 0 bottom
R352  -  [R1005_R_SP]  155.4 106.25 0 bottom
R353  -  [R1005_R_SP]  177 66.4 90 bottom
R354  -  [R1005_R_SP]  177 75.65 90 bottom
R355  -  [R1005_R_SP]  177 84.9 90 bottom
R356  -  [R1005_R_SP]  177 94.15 90 bottom
R357  -  [R1005_R_SP]  177 105.25 90 bottom
R358  -  [R1005_R_SP]  177 114.5 90 bottom
R359  -  [R1005_R_SP]  177 123.75 90 bottom
R360  -  [R1005_R_SP]  177 133 90 bottom
RV1  -  [V2125_R_SP]  79.75 136.75 180 top
S1  -  [CHS_04TB_R_SP]  91 131.75 0 top
S2  -  [SKHMQKE010_R_SP]  134.5 116.5 90 top
T2  -  [750342424_D_SP]  205 23.75 0 top
T3  -  [SUMIDA_PQ2620_D_SP]  82.75 17.5 270 top
TP1  -  [TP_TH1_0_L1_6_D_SP]  33.5 29.75 0 top
TP2  -  [TP_TH1_0_L1_6_D_SP]  37.75 5.75 0 top
TP3  -  [TP_TH1_0_L1_6_D_SP]  149.5 34.5 90 top
TP4  -  [TP_TH1_0_L1_6_D_SP]  165.75 36 270 top
TP5  -  [TP_TH1_0_L1_6_D_SP]  177.5 5 0 top
TP6  -  [TP_TH1_0_L1_6_D_SP]  77.5 122.75 0 top
TP7  -  [TP_TH1_0_L1_6_D_SP]  92.25 116.75 180 top
TP8  -  [TP_TH1_0_L1_6_D_SP]  82.75 116.75 180 top
TP9  -  [TP_TH1_0_L1_6_D_SP]  122.75 116.75 90 top
TP10  -  [TP_TH1_0_L1_6_D_SP]  122.75 119.25 90 top
TP11  -  [TP_TH1_0_L1_6_D_SP]  122.75 121.75 90 top
TP12  -  [TP_TH1_0_L1_6_D_SP]  122.75 124.25 90 top
TP13  -  [TP_TH1_0_L1_6_D_SP]  121 138 90 top
TP14  -  [TP_TH1_0_L1_6_D_SP]  118.5 138 90 top
TP15  -  [TP_TH1_0_L1_6_D_SP]  115.5 138.25 90 top
TP16  -  [TP_TH1_0_L1_6_D_SP]  113 138.25 0 top
TP17  -  [TP_TH1_0_L1_6_D_SP]  70.25 137 180 top
TP18  -  [TP_TH1_0_L1_6_D_SP]  70.25 127.75 180 top
TP19  -  [TP_TH1_0_L1_6_D_SP]  70.25 118.5 180 top
TP20  -  [TP_TH1_0_L1_6_D_SP]  70.25 109.25 180 top
TP21  -  [TP_TH1_0_L1_6_D_SP]  67 101.25 180 top
TP22  -  [TP_TH1_0_L1_6_D_SP]  67 92 180 top
TP23  -  [TP_TH1_0_L1_6_D_SP]  67 82.75 180 top
TP24  -  [TP_TH1_0_L1_6_D_SP]  67 73.5 180 top
TP25  -  [TP_TH1_0_L1_6_D_SP]  59 140.75 180 top
TP26  -  [TP_TH1_0_L1_6_D_SP]  59 131.5 180 top
TP27  -  [TP_TH1_0_L1_6_D_SP]  59 122.25 180 top
TP28  -  [TP_TH1_0_L1_6_D_SP]  59 113 180 top
TP29  -  [TP_TH1_0_L1_6_D_SP]  59 100.15 180 top
TP30  -  [TP_TH1_0_L1_6_D_SP]  59 90.9 180 top
TP31  -  [TP_TH1_0_L1_6_D_SP]  59 81.65 180 top
TP32  -  [TP_TH1_0_L1_6_D_SP]  59 72.4 180 top
TP33  -  [TP_TH1_0_L1_6_D_SP]  87 109.5 270 top
TP34  -  [TP_TH1_0_L1_6_D_SP]  96.25 109.5 270 top
TP35  -  [TP_TH1_0_L1_6_D_SP]  105.5 109.5 270 top
TP36  -  [TP_TH1_0_L1_6_D_SP]  114.75 109.5 270 top
TP37  -  [TP_TH1_0_L1_6_D_SP]  123.85 106.3 270 top
TP38  -  [TP_TH1_0_L1_6_D_SP]  133.1 106.3 270 top
TP39  -  [TP_TH1_0_L1_6_D_SP]  142.35 106.3 270 top
TP40  -  [TP_TH1_0_L1_6_D_SP]  151.6 106.3 270 top
TP41  -  [TP_TH1_0_L1_6_D_SP]  83.25 98.25 270 top
TP42  -  [TP_TH1_0_L1_6_D_SP]  92.5 98.25 270 top
TP43  -  [TP_TH1_0_L1_6_D_SP]  101.75 98.25 270 top
TP44  -  [TP_TH1_0_L1_6_D_SP]  111 98.25 270 top
TP45  -  [TP_TH1_0_L1_6_D_SP]  123.85 98.25 270 top
TP46  -  [TP_TH1_0_L1_6_D_SP]  133.1 98.25 270 top
TP47  -  [TP_TH1_0_L1_6_D_SP]  142.35 98.25 270 top
TP48  -  [TP_TH1_0_L1_6_D_SP]  151.6 98.25 270 top
TP49  -  [TP_TH1_0_L1_6_D_SP]  177.75 71.25 0 top
TP50  -  [TP_TH1_0_L1_6_D_SP]  177.75 80.5 0 top
TP51  -  [TP_TH1_0_L1_6_D_SP]  177.75 89.75 0 top
TP52  -  [TP_TH1_0_L1_6_D_SP]  177.75 99 0 top
TP53  -  [TP_TH1_0_L1_6_D_SP]  173.75 106.75 0 top
TP54  -  [TP_TH1_0_L1_6_D_SP]  173.75 116 0 top
TP55  -  [TP_TH1_0_L1_6_D_SP]  173.75 125.25 0 top
TP56  -  [TP_TH1_0_L1_6_D_SP]  173.75 134.5 0 top
TP57  -  [TP_TH1_0_L1_6_D_SP]  185 62.4 0 top
TP58  -  [TP_TH1_0_L1_6_D_SP]  185 71.65 0 top
TP59  -  [TP_TH1_0_L1_6_D_SP]  185 80.9 0 top
TP60  -  [TP_TH1_0_L1_6_D_SP]  185 90.15 0 top
TP61  -  [TP_TH1_0_L1_6_D_SP]  185 103 0 top
TP62  -  [TP_TH1_0_L1_6_D_SP]  185 112.25 0 top
TP63  -  [TP_TH1_0_L1_6_D_SP]  185 121.5 0 top
TP64  -  [TP_TH1_0_L1_6_D_SP]  185 130.75 0 top
TP65  -  [TP_TH1_0_L1_6_D_SP]  59 134.75 180 top
TP66  -  [TP_TH1_0_L1_6_D_SP]  59 125.5 180 top
TP67  -  [TP_TH1_0_L1_6_D_SP]  59 116.25 180 top
TP68  -  [TP_TH1_0_L1_6_D_SP]  59 107 180 top
TP69  -  [TP_TH1_0_L1_6_D_SP]  59 94.15 180 top
TP70  -  [TP_TH1_0_L1_6_D_SP]  59 84.9 180 top
TP71  -  [TP_TH1_0_L1_6_D_SP]  59 75.65 180 top
TP72  -  [TP_TH1_0_L1_6_D_SP]  59 66.4 180 top
TP73  -  [TP_TH1_0_L1_6_D_SP]  89.25 98.25 270 top
TP74  -  [TP_TH1_0_L1_6_D_SP]  98.5 98.25 270 top
TP75  -  [TP_TH1_0_L1_6_D_SP]  107.75 98.25 270 top
TP76  -  [TP_TH1_0_L1_6_D_SP]  117 98.25 270 top
TP77  -  [TP_TH1_0_L1_6_D_SP]  129.85 98.25 270 top
TP78  -  [TP_TH1_0_L1_6_D_SP]  139.1 98.25 270 top
TP79  -  [TP_TH1_0_L1_6_D_SP]  148.35 98.25 270 top
TP80  -  [TP_TH1_0_L1_6_D_SP]  157.6 98.25 270 top
TP81  -  [TP_TH1_0_L1_6_D_SP]  185 68.4 0 top
TP82  -  [TP_TH1_0_L1_6_D_SP]  185 77.65 0 top
TP83  -  [TP_TH1_0_L1_6_D_SP]  185 86.9 0 top
TP84  -  [TP_TH1_0_L1_6_D_SP]  185 96.15 0 top
TP85  -  [TP_TH1_0_L1_6_D_SP]  185 109 0 top
TP86  -  [TP_TH1_0_L1_6_D_SP]  185 118.25 0 top
TP87  -  [TP_TH1_0_L1_6_D_SP]  185 127.5 0 top
TP88  -  [TP_TH1_0_L1_6_D_SP]  185 136.75 0 top

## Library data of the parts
C1 = ECWFG2J105P1
C2 C3 = 2220CC104KAT1A: alternate symbols: (C2_C5750_R_SP,C3_C5750_R_SP)
C4 C14 C137 C138 = GRM21BR61H475KE51L
C5 C10 = GRM1885C2A470JA01D
C6 C9 C131 C132 = GRM31CC81E226KE11L
C7 = EKY-500ELL471ML15S
C8 C11 C13 C130 = GRM1885C1H102JA01J
C12 C24 C27 C32-C39 C41-C46 C61 C75 C89-C95 C97 C99 C101 C133-C136 C139-C141 = GRM155R71E104KE14D
C15-C21 C129 = GRM31CR71E106MA12K
C22 C103 = GRM1885C1H103JA01J
C23 C25 C28-C31 C40 C102 = GRM188R61A106ME69D
C47 C50 C53 C55 C57-C60 C62 C64 C68 C70 C72-C74 C76 C77 C79 C81 C83 C85-C88 = GRM21BR71E225KE11L
C48 C49 C54 C56 C63 C65 C69 C71 C78 C80 C82 C84 = EKMQ251ELL101ML25S
C66 C67 = EKXF451ELL470MM25S
C96 C98 C100 = GRM1555C1H100RA01D
C104-C127 = C1608X7R1H104K080AA
C128 = 06031A151FAT2A
C142-C165 = GRM1555C1H471JA01J
CN1 = OTB-640NS-B-2P-C
CN2 = 1843606
CN3 = FTSH-120-04-F-DH-A-AEP
CN4 = 878311420
CN5 = OTB-640NS-B-3P-C
D1 = CRH01-12
D2 = FSV20100V-123
D3 = CRZ18
D4 = SMBJ188A-E3_52
D6 = US1MDFQ-13
D7-D11 = CMS10
D13 = CRS30I30A
D14 D16 D18 D20 D22 D24 D26 D28 D30 D32 D34 D36 D38 D40 D42 D44 D46 D48 = CMF01A_LQ_M
D15 D17 D19 D21 D23 D25 D27 D29 D31 D33 D35 D37 D39 D41 D43 D45 D47 D49 = FFSM2065B
D50-D73 = BAS516_L3F
DR1-DR3 = ONEPOINT
DS1-DS4 = SMLD12EN1WT86
FL1 = ACM4520-421-2P-T000
IC1 = LT-20-Lead-Plastic-TSSOP-FE-R-SP-17p
IC2 = LT3086IFE_PBF
IC3 = LTC3803HS6-5_TRMPBF
IC4 = TCR3UF33A
IC5 = TCR3UF18A
IC6 IC8 = TC7MPB9307FT
IC7 = XC2C256-7VQG100C
IC9 IC19-IC21 = OPA172IDCKT
IC10-IC12 = TMCS1100A1QDRQ1
IC13 IC15 IC18 = TC75W57FK
IC14 IC16 IC17 = TC7W08FK
IC22 = ASE-20.000MHZ-LC-T
PC1-PC24 = TLP152_TPL_E
Q1 = TK17V65W
Q2 = TPN7R006PL_L1Q
Q3 Q5 Q7 Q9 Q11 Q13 Q15 Q17 Q19 Q21 Q23 Q25 Q27 Q29 Q31 Q33 Q35 Q37 Q39 Q41 Q43 Q45 Q47 Q49 = TPH9R00CQ5
Q4 Q6 Q8 Q10 Q12 Q14 Q16 Q18 Q20 Q22 Q24 Q26 Q28 Q30 Q32 Q34 Q36 Q38 Q40 Q42 Q44 Q46 Q48 Q50 = SSM3K15AFS-123
R1 R3 R5 R7 R9 R10 R193-R196 R199-R206 = HV73V2BTTD4703D
R2 R80 R82 R84 R88 R90 R92 R96 R98 R101 R104 R106 R108 R112 R114 R116 R120 R122 R124 = ERJ3EKF10R0V
R4 R14 R34 R36 R39 R207 R208 R301-R308 = ERJ3EKF1002V
R6 = ERA3APB6042V
R8 = AAC-0805
R11 R15 = RK73H1JRTTD1502D
R12 = ERJ3EKF1203V
R13 = ERA3AEB4991V
R16 = ERA3ARB5622V
R17 R86 R94 R103 R110 R118 R126 R154 R245-R247 R249 R251 R253 R255 R257 R258 R260 R262 R264 R266 R268 R270 R272 R274 R276 R278 R280 R282 R284 R286 R288 R298 R299 = ERJ3GEY0R00V
R18 = ERJ3EKF1000V
R19 = KRL1632E-M-R150-F-T5
R20 R21 R23 R25 = ERJ6GEY0R00V
R22 R295 = ERJ2RKF1003X
R24 R297 = ERJ2RKF2703X
R26 = ERJ2RKF3300X
R27 = ERJ2RKF2202X
R28 = ERJ3EKF3302V
R29 = ERJ3EKF5102V
R30 = ERJ3EKF4701V
R31 R300 = ERJ3EKF1001V
R32 = ERJ3EKF2202V
R33 = WSLP0603R0470FEA
R40-R55 R58-R73 R136 R139 R142 R149-R153 R214-R237 R241 R243 R313-R336 = ERJ2RKF1002X
R56 R57 R74 R137 R140 R143 R156-R167 R192 R198 R238-R240 R242 R244 R309-R312 = ERJ2GE0R00X
R75-R79 = ERJ2RKF22R0X
R81 R83 R85 R87 R89 R91 R93 R95 R97 R99 R100 R102 R105 R107 R109 R111 R113 R115 R117 R119 R121 R123 R125 R127 = ERJ2RKF2700X
R128 R129 R134 R135 = ERJ3RBD2002V
R130-R133 = ERJ3RBD3002V
R138 R141 R144 = ERJ2RKF2002X
R145-R148 R337-R360 = ERJ2RKF1001X
R155 = ERJP06J471V
R168-R191 = ERJ3EKF22R0V
R197 = ERJ3EKF2200V
R209-R213 = ERJ2RKF1000X
R289-R294 = RK73G1ETTP1002D
R296 = ERJ2RKF1603X
RV1 = NV73A2ATTE8.2
S1 = CHS-04TB
S2 = SKHMQKE010
T2 = 750342424
T3 = 11328-T074
TP1-TP88 = TP-TH1.0-L1.6

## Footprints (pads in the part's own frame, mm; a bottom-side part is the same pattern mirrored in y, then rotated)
1843606_D_SP
  round 2 hole 1.2: 1(1.75,0) 2(-1.75,0)
750342424_D_SP
  round 2.2 hole 1.4: 1(-17.5,-15.3) 2(-12.5,-15.3) 3(-7.5,-15.3) 4(-2.5,-15.3) 7(12.5,-15.3) 8(17.5,-15.3) 9(17.5,15.3) 10(12.5,15.3) 12(2.5,15.3) 13(-2.5,15.3) 15(-12.5,15.3) 16(-17.5,15.3)
878311420_D_SP
  round 0.01 hole 1 unplated: (5,0)
  round 1.4 hole 0.9: 1(-6,-1) 2(-6,1) 3(-4,-1) 4(-4,1) 5(-2,-1) 6(-2,1) 7(0,-1) 8(0,1) 9(2,-1) 10(2,1) 11(4,-1) 12(4,1) 13(6,-1) 14(6,1)
ABRACON_ASE_3_2X2_5__1
  rect 1.3x1.1 smd: 1(-1.05,-0.825) 2(1.05,-0.825) 3(1.05,0.825) 4(-1.05,0.825)
C1005_R_SP
  rect 0.5x0.6 smd: 1(-0.5,0) 2(0.5,0)
C1608_R_SP
  rect 0.9x0.85 smd: 1(-0.85,0) 2(0.85,0)
C2125_R_SP
  rect 1.05x1.3 smd: 1(-0.975,0) 2(0.975,0)
C3216_R_SP
  rect 1.2x1.7 smd: 1(-1.6,0) 2(1.6,0)
C5750_R_SP
  custom 0.487x0.487 smd: 1(-2.85,0) 2(2.85,0)
C_27_0X10_5_P22_5_D__1
  round 2 hole 1.2: 1(-11.25,0) 2(11.25,0)
CA_D18_0_P7_5_D_SP
  round 1.6 hole 1: 1(-3.75,0) 2(3.75,0)
CA_NICHEMI_D16_0_P7__1
  round 1.6 hole 1: 1(-3.75,0) 2(3.75,0)
CHS_04TB_R_SP
  rect 0.76x1.27 smd: 1(-1.905,-3.81) 2(-0.635,-3.81) 3(0.635,-3.81) 4(1.905,-3.81) 5(1.905,3.81) 6(0.635,3.81) 7(-0.635,3.81) 8(-1.905,3.81)
D_ROHM_1608_R_SP
  rect 0.8x0.8 smd: A(-0.825,0) K(0.825,0)
DIODES_D_FLAT_R_SP
  rect 1.85x1.7 smd: A(-2.325,0) K(2.325,0)
FTSH_120_04_X_DH_A_A_1
  rect 0.75x1.36 smd: 1(12.065,-3.375) 3(10.795,-3.375) 5(9.525,-3.375) 7(8.255,-3.375) 9(6.985,-3.375) 11(5.715,-3.375) 13(4.445,-3.375) 15(3.175,-3.375) 17(1.905,-3.375) 19(0.635,-3.375) 21(-0.635,-3.375) 23(-1.905,-3.375) 25(-3.175,-3.375) 27(-4.445,-3.375) 29(-5.715,-3.375) 31(-6.985,-3.375) 33(-8.255,-3.375) 35(-9.525,-3.375) 37(-10.795,-3.375) 39(-12.065,-3.375)
  rect 0.75x1.62 smd: 2(12.065,-6.245) 4(10.795,-6.245) 6(9.525,-6.245) 8(8.255,-6.245) 10(6.985,-6.245) 12(5.715,-6.245) 14(4.445,-6.245) 16(3.175,-6.245) 18(1.905,-6.245) 20(0.635,-6.245) 22(-0.635,-6.245) 24(-1.905,-6.245) 26(-3.175,-6.245) 28(-4.445,-6.245) 30(-5.715,-6.245) 32(-6.985,-6.245) 34(-8.255,-6.245) 36(-9.525,-6.245) 38(-10.795,-6.245) 40(-12.065,-6.245)
LT_20_LEAD_PLASTIC_T_1
  rect 0.35x1.425 smd: 1(-2.925,-2.987) 2(-2.275,-2.987) 3(-1.625,-2.987) 8(1.625,-2.987) 9(2.275,-2.987) 10(2.925,-2.987) 11(2.925,2.987) 12(2.275,2.987) 13(1.625,2.987) 14(0.975,2.987) 15(0.325,2.987) 16(-0.325,2.987) 17(-0.975,2.987) 18(-1.625,2.987) 19(-2.275,2.987) 20(-2.925,2.987)
  custom 0.445x0.445 smd: 21(0,0.47)
LT_TSOT_23_6_R_SP
  rect 0.62x1.22 smd: 1(-0.95,-1.31) 2(0,-1.31) 3(0.95,-1.31) 4(0.95,1.31) 5(0,1.31) 6(-0.95,1.31)
LT_TSSOP_16_FE_R_SP
  rect 0.35x1.425 smd: 1(-2.275,-2.987) 2(-1.625,-2.987) 3(-0.975,-2.987) 4(-0.325,-2.987) 5(0.325,-2.987) 6(0.975,-2.987) 7(1.625,-2.987) 8(2.275,-2.987) 9(2.275,2.987) 10(1.625,2.987) 11(0.975,2.987) 12(0.325,2.987) 13(-0.325,2.987) 14(-0.975,2.987) 15(-1.625,2.987) 16(-2.275,2.987)
  custom 0.735x0.735 smd: 17(0,0)
ON_PQFN4_8X8_2P_R_SP
  rect 1.2x0.85 smd: 1(-3,-3.825) 2(-1,-3.825) 3(1,-3.825) 4(3,-3.825)
  custom 1.087x1.087 smd: 5(0,1.425)
ON_TO_227_3LD_123_R__1
  rect 1.15x1.45 smd: 1(2.75,0.985) 2(2.75,-0.985)
  custom 1.038x1.038 smd: 3(-1,0)
ONEPOINT_R_SP
  round 0.5 smd: 1(0,0) 2(0,0)
OTB_640NS_B_2P_C_D_S_1
  custom 0.575x0.575 hole 1.3x4.5: 1(0,0) 2(11,0)
OTB_640NS_B_3P_C_D_S_1
  custom 0.575x0.575 hole 1.3x4.5: 1(0,0) 2(11,0) 3(22,0)
R1005_R_SP
  rect 0.5x0.6 smd: 1(-0.5,0) 2(0.5,0)
R1608_R_SP
  rect 0.9x0.85 smd: 1(-0.85,0) 2(0.85,0)
R2125_R_SP
  rect 1.05x1.3 smd: 1(-0.975,0) 2(0.975,0)
R3216_R_SP
  rect 1.2x1.7 smd: 1(-1.6,0) 2(1.6,0)
R_WSL0603_R_SP
  rect 1.02x1.02 smd: 1(-0.76,0) 2(0.76,0)
SKHMQKE010_R_SP
  rect 1.4x1.6 smd: 1(-2.25,-4.2) 2(-2.25,4.2) 3(2.25,-4.2) 4(2.25,4.2) 5(0,4.2)
SUMIDA_PQ2620_D_SP
  round 1.8 hole 1.1: 1(-11.43,-12.7) 2(-7.62,-12.7) 3(-3.81,-12.7) 4(3.81,-12.7) 5(7.62,-12.7) 6(11.43,-12.7) 7(11.43,12.7) 8(7.62,12.7) 9(3.81,12.7) 10(-3.81,12.7) 11(-7.62,12.7) 12(-11.43,12.7)
TDK_ACM4520_R_SP
  rect 1.25x0.95 smd: 1(-2.375,1) 2(-2.375,-1) 3(2.375,-1) 4(2.375,1)
TI_D8_R_SP
  rect 0.6x1.635 smd: 1(-1.905,-2.683) 2(-0.635,-2.683) 3(0.635,-2.683) 4(1.905,-2.683) 5(1.905,2.683) 6(0.635,2.683) 7(-0.635,2.683) 8(-1.905,2.683)
TI_DCK5_R_SP
  rect 0.4x0.9 smd: 1(-0.65,-1.1) 2(0,-1.1) 3(0.65,-1.1) 4(0.65,1.1) 5(-0.65,1.1)
TO_2_2H1B_GSD_123_R__1
  rect 0.6x0.6 smd: 1(-0.5,-0.7) 2(0.5,-0.7) 3(0,0.7)
TO_2_3X1S_R_SP
  rect 0.4x0.4 smd: 1(-0.975,-1.55) 2(-0.325,-1.55) 3(0.325,-1.55) 4(0.975,-1.55)
  round 0.1 smd: 5(0.975,1.65) 6(0.325,1.65) 7(-0.325,1.65) 8(-0.975,1.65)
TO_2_5W1A_R_SP
  rect 0.85x1.45 smd: 1(-1.905,-2.75) 2(-0.635,-2.75) 3(0.635,-2.75) 4(1.905,-2.75)
  custom 0.05x0.05 smd: 5(1.905,3) 6(0.635,3) 7(-0.635,3) 8(-1.905,3)
TO_2_8T1A_R_SP
  rect 1.1x1 smd: 1(-3,-3.925) 2(-1,-3.925) 3(1,-3.925) 4(3,-3.925)
  custom 1.125x1.125 smd: 5(0,1.425)
TO_3_2A1A_12_R_SP
  rect 1.2x1.2 smd: 1(-1.4,0) 2(1.4,0)
TO_3_2A1S_R_SP
  rect 1.2x1.2 smd: A(-1.4,0) K(1.4,0)
TO_3_4E1A_R_SP
  rect 1.4x2.1 smd: A(-2.2,0) K(2.2,0)
TO_3_4E1S_R_SP
  rect 1.4x2.1 smd: A(-2.2,0) K(2.2,0)
TO_11_4L1S_R_SP
  rect 0.6x1.3 smd: 1(-1.27,-3.35) 3(1.27,-3.35) 4(1.27,3.35) 5(0,3.35) 6(-1.27,3.35)
TO_ESC_R_SP
  rect 0.6x0.8 smd: A(-0.85,0) K(0.85,0)
TO_SSOP5_P_0_95_R_SP
  rect 0.8x1 smd: 1(-0.95,-1.2) 3(0.95,-1.2) 4(0.95,1.2) 5(-0.95,1.2)
  rect 0.6x1 smd: 2(0,-1.2)
TO_SSOP8_P_0_50A_R_S_1
  rect 0.3x0.7 smd: 1(-0.75,-1.35) 2(-0.25,-1.35) 3(0.25,-1.35) 4(0.75,-1.35) 5(0.75,1.35) 6(0.25,1.35) 7(-0.25,1.35) 8(-0.75,1.35)
TO_TSSOP20B_R_SP
  rect 0.35x1.4 smd: 1(-2.925,-3) 2(-2.275,-3) 3(-1.625,-3) 4(-0.975,-3) 5(-0.325,-3) 6(0.325,-3) 7(0.975,-3) 8(1.625,-3) 9(2.275,-3) 10(2.925,-3) 11(2.925,3) 12(2.275,3) 13(1.625,3) 14(0.975,3) 15(0.325,3) 16(-0.325,3) 17(-0.975,3) 18(-1.625,3) 19(-2.275,3) 20(-2.925,3)
TP_TH1_0_L1_6_D_SP
  round 1.6 hole 1: 1(0,0)
V2125_R_SP
  rect 1.05x1.3 smd: 1(-0.975,0) 2(0.975,0)
VISHAY_DO_214AA_R_SP
  rect 1.716x2.18 smd: A(-1.937,0) K(1.937,0)
XI_VQFP100_R_SP
  rect 0.3x1.4 smd: 1(-6,-7.8) 2(-5.5,-7.8) 3(-5,-7.8) 4(-4.5,-7.8) 5(-4,-7.8) 6(-3.5,-7.8) 7(-3,-7.8) 8(-2.5,-7.8) 9(-2,-7.8) 10(-1.5,-7.8) 11(-1,-7.8) 12(-0.5,-7.8) 13(0,-7.8) 14(0.5,-7.8) 15(1,-7.8) 16(1.5,-7.8) 17(2,-7.8) 18(2.5,-7.8) 19(3,-7.8) 20(3.5,-7.8) 21(4,-7.8) 22(4.5,-7.8) 23(5,-7.8) 24(5.5,-7.8) 25(6,-7.8) 51(6,7.8) 52(5.5,7.8) 53(5,7.8) 54(4.5,7.8) 55(4,7.8) 56(3.5,7.8) 57(3,7.8) 58(2.5,7.8) 59(2,7.8) 60(1.5,7.8) 61(1,7.8) 62(0.5,7.8) 63(0,7.8) 64(-0.5,7.8) 65(-1,7.8) 66(-1.5,7.8) 67(-2,7.8) 68(-2.5,7.8) 69(-3,7.8) 70(-3.5,7.8) 71(-4,7.8) 72(-4.5,7.8) 73(-5,7.8) 74(-5.5,7.8) 75(-6,7.8)
  rect 1.4x0.3 smd: 26(7.8,-6) 27(7.8,-5.5) 28(7.8,-5) 29(7.8,-4.5) 30(7.8,-4) 31(7.8,-3.5) 32(7.8,-3) 33(7.8,-2.5) 34(7.8,-2) 35(7.8,-1.5) 36(7.8,-1) 37(7.8,-0.5) 38(7.8,0) 39(7.8,0.5) 40(7.8,1) 41(7.8,1.5) 42(7.8,2) 43(7.8,2.5) 44(7.8,3) 45(7.8,3.5) 46(7.8,4) 47(7.8,4.5) 48(7.8,5) 49(7.8,5.5) 50(7.8,6) 76(-7.8,6) 77(-7.8,5.5) 78(-7.8,5) 79(-7.8,4.5) 80(-7.8,4) 81(-7.8,3.5) 82(-7.8,3) 83(-7.8,2.5) 84(-7.8,2) 85(-7.8,1.5) 86(-7.8,1) 87(-7.8,0.5) 88(-7.8,0) 89(-7.8,-0.5) 90(-7.8,-1) 91(-7.8,-1.5) 92(-7.8,-2) 93(-7.8,-2.5) 94(-7.8,-3) 95(-7.8,-3.5) 96(-7.8,-4) 97(-7.8,-4.5) 98(-7.8,-5) 99(-7.8,-5.5) 100(-7.8,-6)

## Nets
5V_IN: C23.1 C24.1 CN2.2 D13.K FL1.2 RV1.2
5V_RTN: C23.2 C24.2 CN2.1 D13.A FL1.1 RV1.1
GND: C1.2 C2.2 C3.2 C4.2 C6.2 C7.2 C8.1 C9.2 C10.2 C11.2 C12.2 C13.2 C14.2 C15.2 C16.2 C20.2 C21.2 C56.2 C66.2 C67.2 C71.2 C84.2 C103.2 C129.2 C130.2 C131.2 C132.2 C137.2 C138.2 CN1.2 D3.A IC1.15 IC1.16 IC1.20 IC1.21 IC2.1 IC2.8 IC2.9 IC2.16 IC2.17 IC3.2 IC10.3 IC10.4 IC11.3 IC11.4 IC12.3 IC12.4 R8.1 R11.1 R13.2 R15.2 R16.1 R19.2 R26.2 R31.2 R32.2 R33.2 R34.2 R196.2 R197.2 R202.2 R206.2 R207.2 R208.2 R298.2 R299.2 R300.2 R307.2 R308.2 T2.4 T2.8 T3.6 T3.10 T3.11 TP2.1
GND_D: C25.2 C27.2 C28.2 C29.2 C30.2 C31.2 C32.2 C33.2 C34.2 C35.2 C36.2 C37.2 C38.2 C39.2 C40.2 C41.2 C42.2 C43.2 C44.2 C45.2 C46.2 C61.2 C75.2 C89.2 C90.2 C91.2 C92.2 C93.2 C94.2 C95.2 C97.2 C99.2 C101.2 C102.2 C133.2 C134.2 C135.2 C136.2 C139.2 C140.2 C141.2 CN3.1 CN3.2 CN3.15 CN3.16 CN3.29 CN3.31 CN3.33 CN3.35 CN3.37 CN3.39 CN4.1 CN4.3 CN4.5 CN4.7 CN4.9 CN4.11 CN4.13 FL1.4 IC4.2 IC5.2 IC6.10 IC7.21 IC7.25 IC7.31 IC7.62 IC7.69 IC7.75 IC7.84 IC7.100 IC8.10 IC9.2 IC10.5 IC11.5 IC12.5 IC13.4 IC14.4 IC15.4 IC16.4 IC16.5 IC16.6 IC17.4 IC18.4 IC19.2 IC20.2 IC21.2 IC22.2 Q4.2 Q6.2 Q8.2 Q10.2 Q12.2 Q14.2 Q16.2 Q18.2 Q20.2 Q22.2 Q24.2 Q26.2 Q28.2 Q30.2 Q32.2 Q34.2 Q36.2 Q38.2 Q40.2 Q42.2 Q44.2 Q46.2 Q48.2 Q50.2 R134.2 R135.2 R138.1 R141.1 R144.1 R242.1 R244.1 R290.2 R292.1 R294.1 R298.1 R299.1 R313.2 R314.2 R315.2 R316.2 R317.2 R318.2 R319.2 R320.2 R321.2 R322.2 R323.2 R324.2 R325.2 R326.2 R327.2 R328.2 R329.2 R330.2 R331.2 R332.2 R333.2 R334.2 R335.2 R336.2 S1.5 S1.6 S1.7 S1.8 S2.3 S2.4 S2.5
AMP_IU_NI: C96.2 IC19.3 R136.2 R138.2
AMP_IU_OUT: C96.1 IC19.4 R136.1 R137.2
AMP_IV_NI: C98.2 IC20.3 R139.2 R141.2
AMP_IV_OUT: C98.1 IC20.4 R139.1 R140.2
AMP_IW_NI: C100.2 IC21.3 R142.2 R144.2
AMP_IW_OUT: C100.1 IC21.4 R142.1 R143.2
BS_U1: D14.K R80.2
BS_U2: D16.K R82.2
BS_U3: D18.K R84.2
BS_U5: D20.K R88.2
BS_U6: D22.K R90.2
BS_U7: D24.K R92.2
BS_V1: D26.K R96.2
BS_V2: D28.K R98.2
BS_V3: D30.K R101.2
BS_V5: D32.K R104.2
BS_V6: D34.K R106.2
BS_V7: D36.K R108.2
BS_W1: D38.K R112.2
BS_W2: D40.K R114.2
BS_W3: D42.K R116.2
BS_W5: D44.K R120.2
BS_W6: D46.K R122.2
BS_W7: D48.K R124.2
CN_TCK: CN4.6 R75.1
CN_TDI: CN4.10 R78.1
CN_TDO: CN4.8 R77.1
CN_TMS: CN4.4 R76.1
CP_MODE: IC6.6 IC7.7 R52.2
CP_RESET: IC6.7 IC7.8 R53.2
CP_RSV1: IC6.8 IC7.9 R54.2
CP_RSV2: IC6.9 IC7.10 R55.2
CP_RSV3: IC7.60 IC8.8 R72.2
CP_RSV4: IC7.61 IC8.9 R73.2
CP_SW: IC7.99 R209.2
CP_TCK: IC6.3 IC7.48 R49.2 R75.2
CP_TDI: IC6.4 IC7.45 R50.2 R78.2
CP_TDO: IC6.2 IC7.83 R48.2 R77.2
CP_TMS: IC6.5 IC7.47 R51.2 R76.2
CP_TP9: IC7.11 TP9.1
CP_TP10: IC7.12 TP10.1
CP_TP11: IC7.13 TP11.1
CP_TP12: IC7.14 TP12.1
CP_TP13: IC7.23 TP13.1
CP_TP14: IC7.24 TP14.1
CP_TP15: IC7.27 TP15.1
CP_TP16: IC7.28 TP16.1
CP_UH: IC7.30 IC8.2 R66.2
CP_UL: IC7.32 IC8.3 R67.2
CP_VGS_U1: IC7.65 Q4.1 R313.1 TP17.1
CP_VGS_U2: IC7.66 Q6.1 R314.1 TP18.1
CP_VGS_U3: IC7.67 Q8.1 R315.1 TP19.1
CP_VGS_U4: IC7.68 Q10.1 R316.1 TP20.1
CP_VGS_U5: IC7.70 Q12.1 R317.1 TP21.1
CP_VGS_U6: IC7.71 Q14.1 R318.1 TP22.1
CP_VGS_U7: IC7.72 Q16.1 R319.1 TP23.1
CP_VGS_U8: IC7.73 Q18.1 R320.1 TP24.1
CP_VGS_V1: IC7.76 Q20.1 R321.1 TP33.1
CP_VGS_V2: IC7.77 Q22.1 R322.1 TP34.1
CP_VGS_V3: IC7.78 Q24.1 R323.1 TP35.1
CP_VGS_V4: IC7.79 Q26.1 R324.1 TP36.1
CP_VGS_V5: IC7.80 Q28.1 R325.1 TP37.1
CP_VGS_V6: IC7.81 Q30.1 R326.1 TP38.1
CP_VGS_V7: IC7.82 Q32.1 R327.1 TP39.1
CP_VGS_V8: IC7.85 Q34.1 R328.1 TP40.1
CP_VGS_W1: IC7.89 Q36.1 R329.1 TP49.1
CP_VGS_W2: IC7.90 Q38.1 R330.1 TP50.1
CP_VGS_W3: IC7.91 Q40.1 R331.1 TP51.1
CP_VGS_W4: IC7.92 Q42.1 R332.1 TP52.1
CP_VGS_W5: IC7.93 Q44.1 R333.1 TP53.1
CP_VGS_W6: IC7.94 Q46.1 R334.1 TP54.1
CP_VGS_W7: IC7.95 Q48.1 R335.1 TP55.1
CP_VGS_W8: IC7.96 Q50.1 R336.1 TP56.1
CP_VH: IC7.33 IC8.4 R68.2
CP_VL: IC7.34 IC8.5 R69.2
CP_WH: IC7.35 IC8.6 R70.2
CP_WL: IC7.36 IC8.7 R71.2
CPLD_CLK: IC7.22 R79.2
DBG_LED1: DS1.K IC7.49
DBG_LED2: DS2.K IC7.50
DBG_LED3: DS3.K IC7.52
DBG_LED4: DS4.K IC7.53
DBG_SW1: IC7.54 R210.2
DBG_SW2: IC7.55 R211.2
DBG_SW3: IC7.56 R212.2
DBG_SW4: IC7.58 R213.2
GD_U1: Q3.4 R176.2 R214.1 R245.2
GD_U2: Q5.4 R177.2 R215.1 R246.2
